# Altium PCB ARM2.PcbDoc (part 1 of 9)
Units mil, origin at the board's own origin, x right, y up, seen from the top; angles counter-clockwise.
Board outline 4700.79 x 3937.01 mil, 6 copper layers (Top Layer, GND02, ART03, ART04, PWR05, Bottom Layer); 697 components, 508 nets, 2326 pads, 1231 vias.
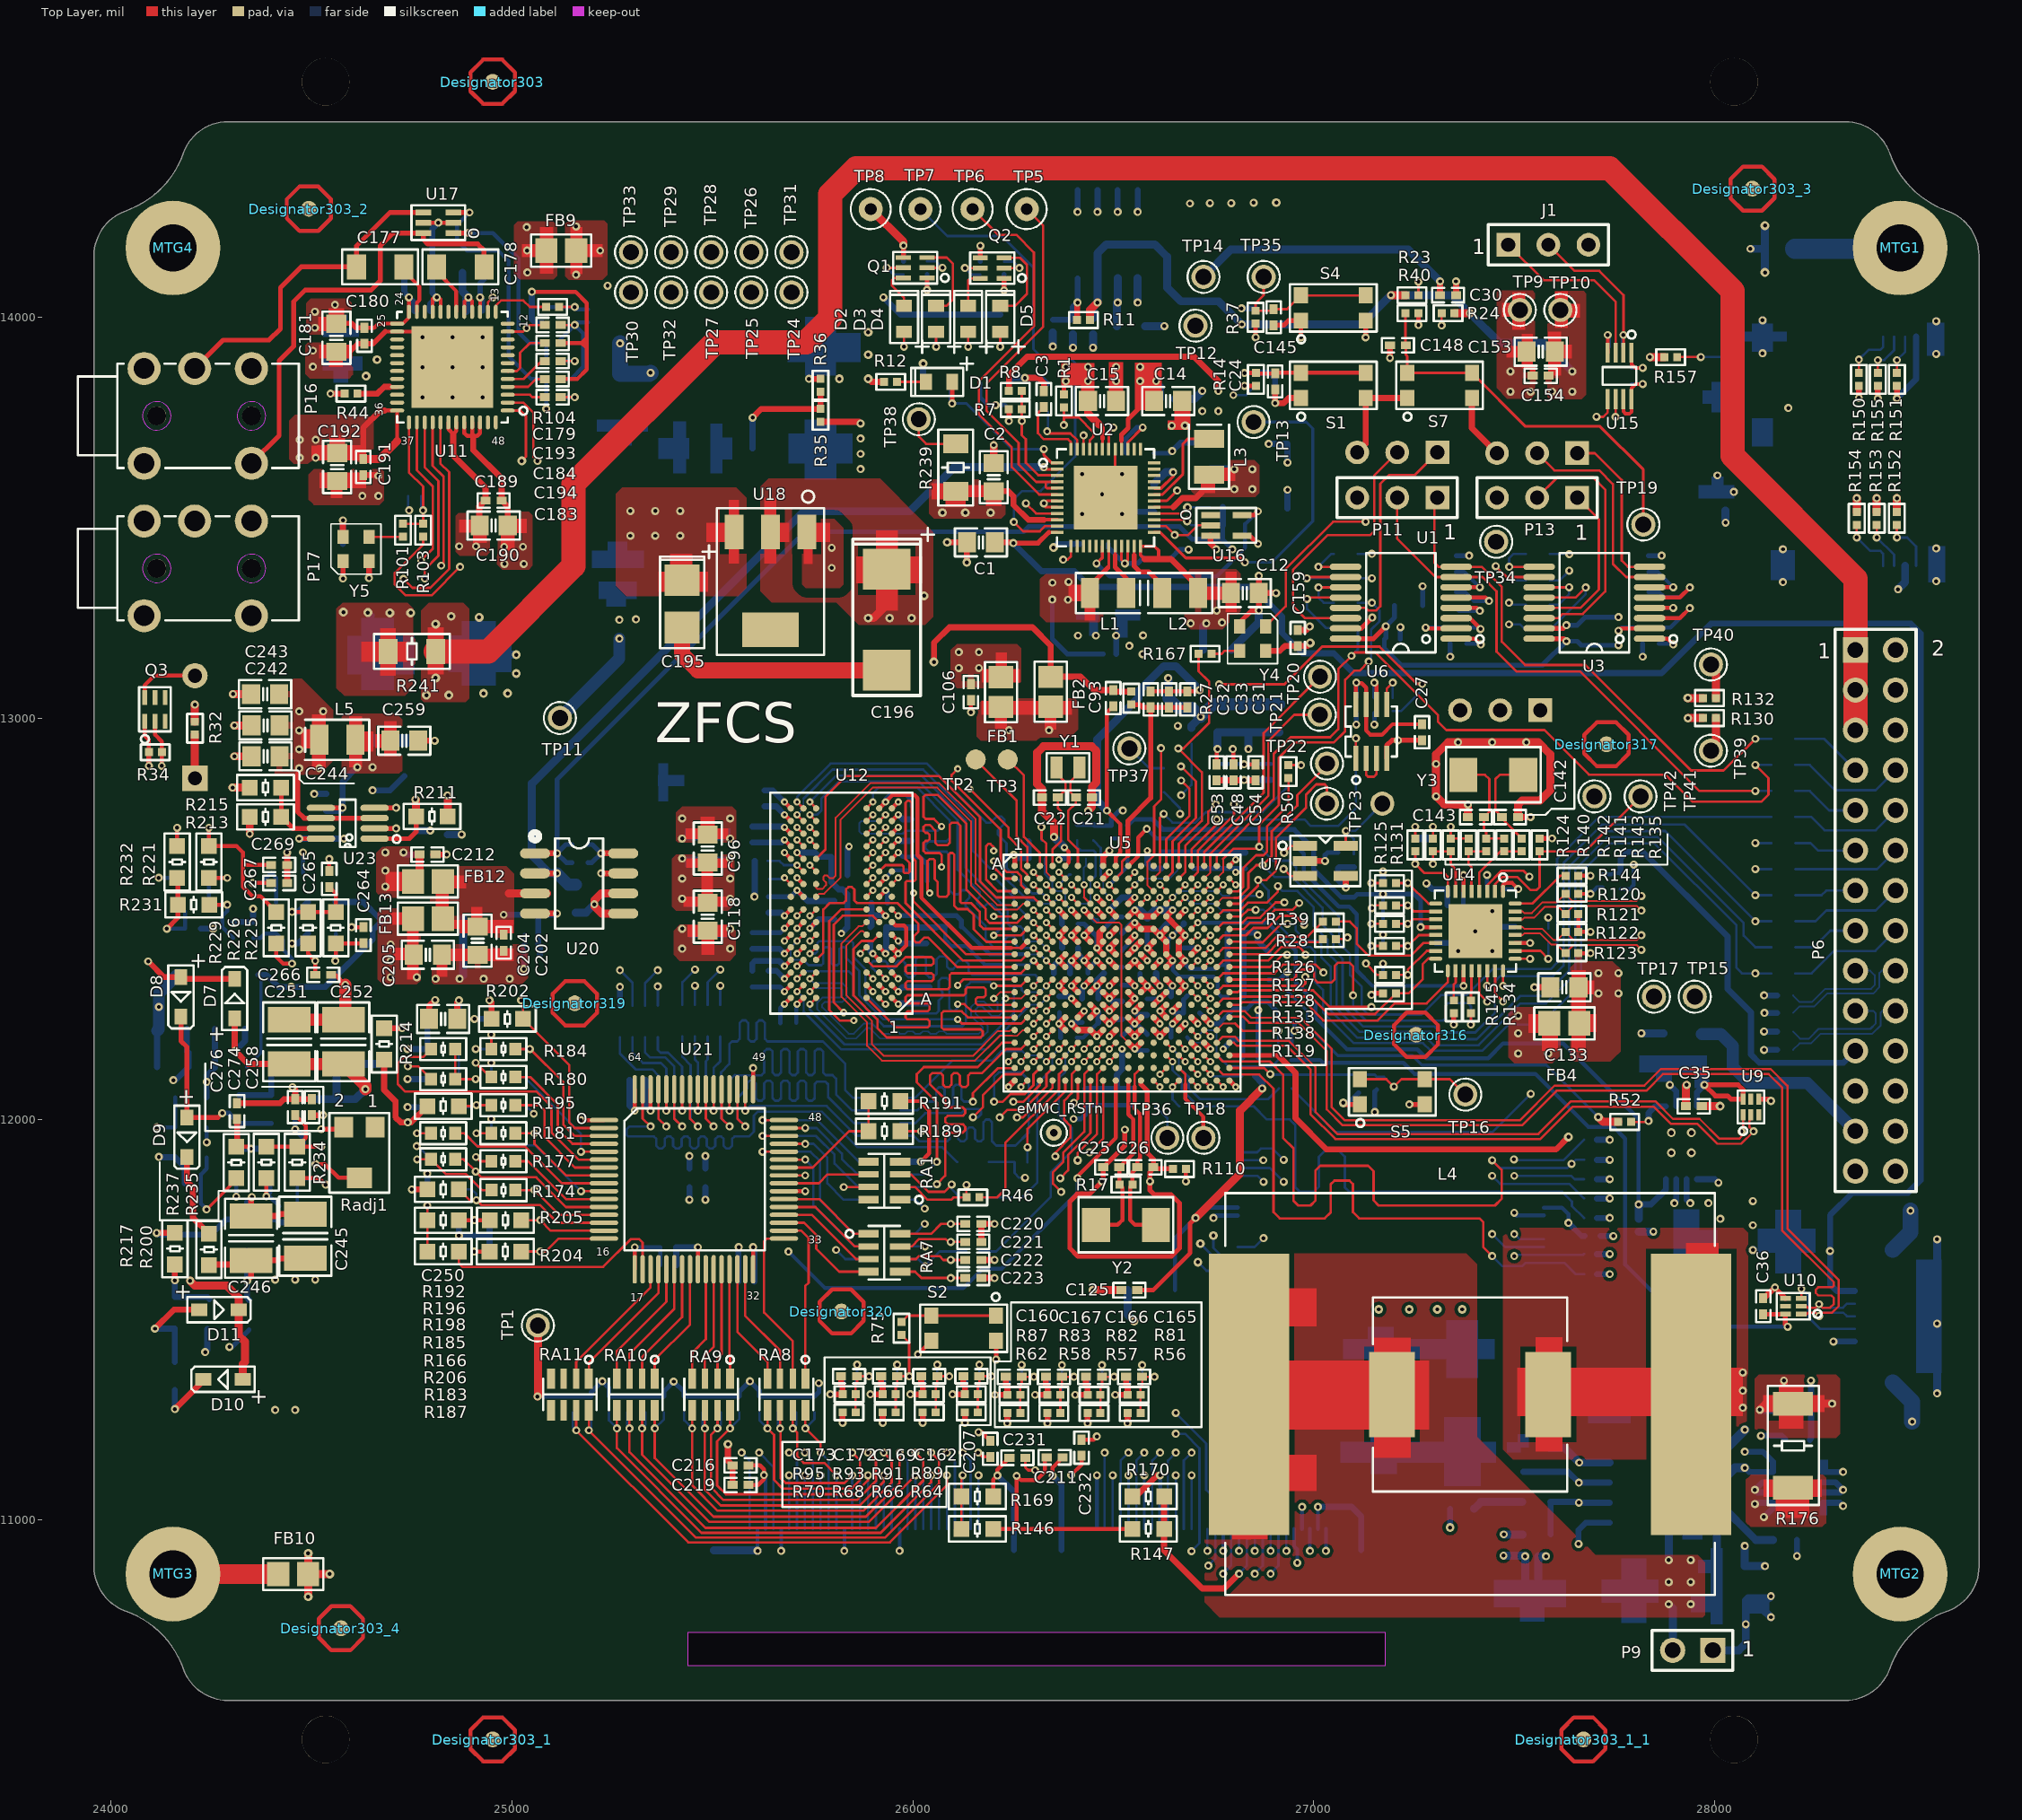
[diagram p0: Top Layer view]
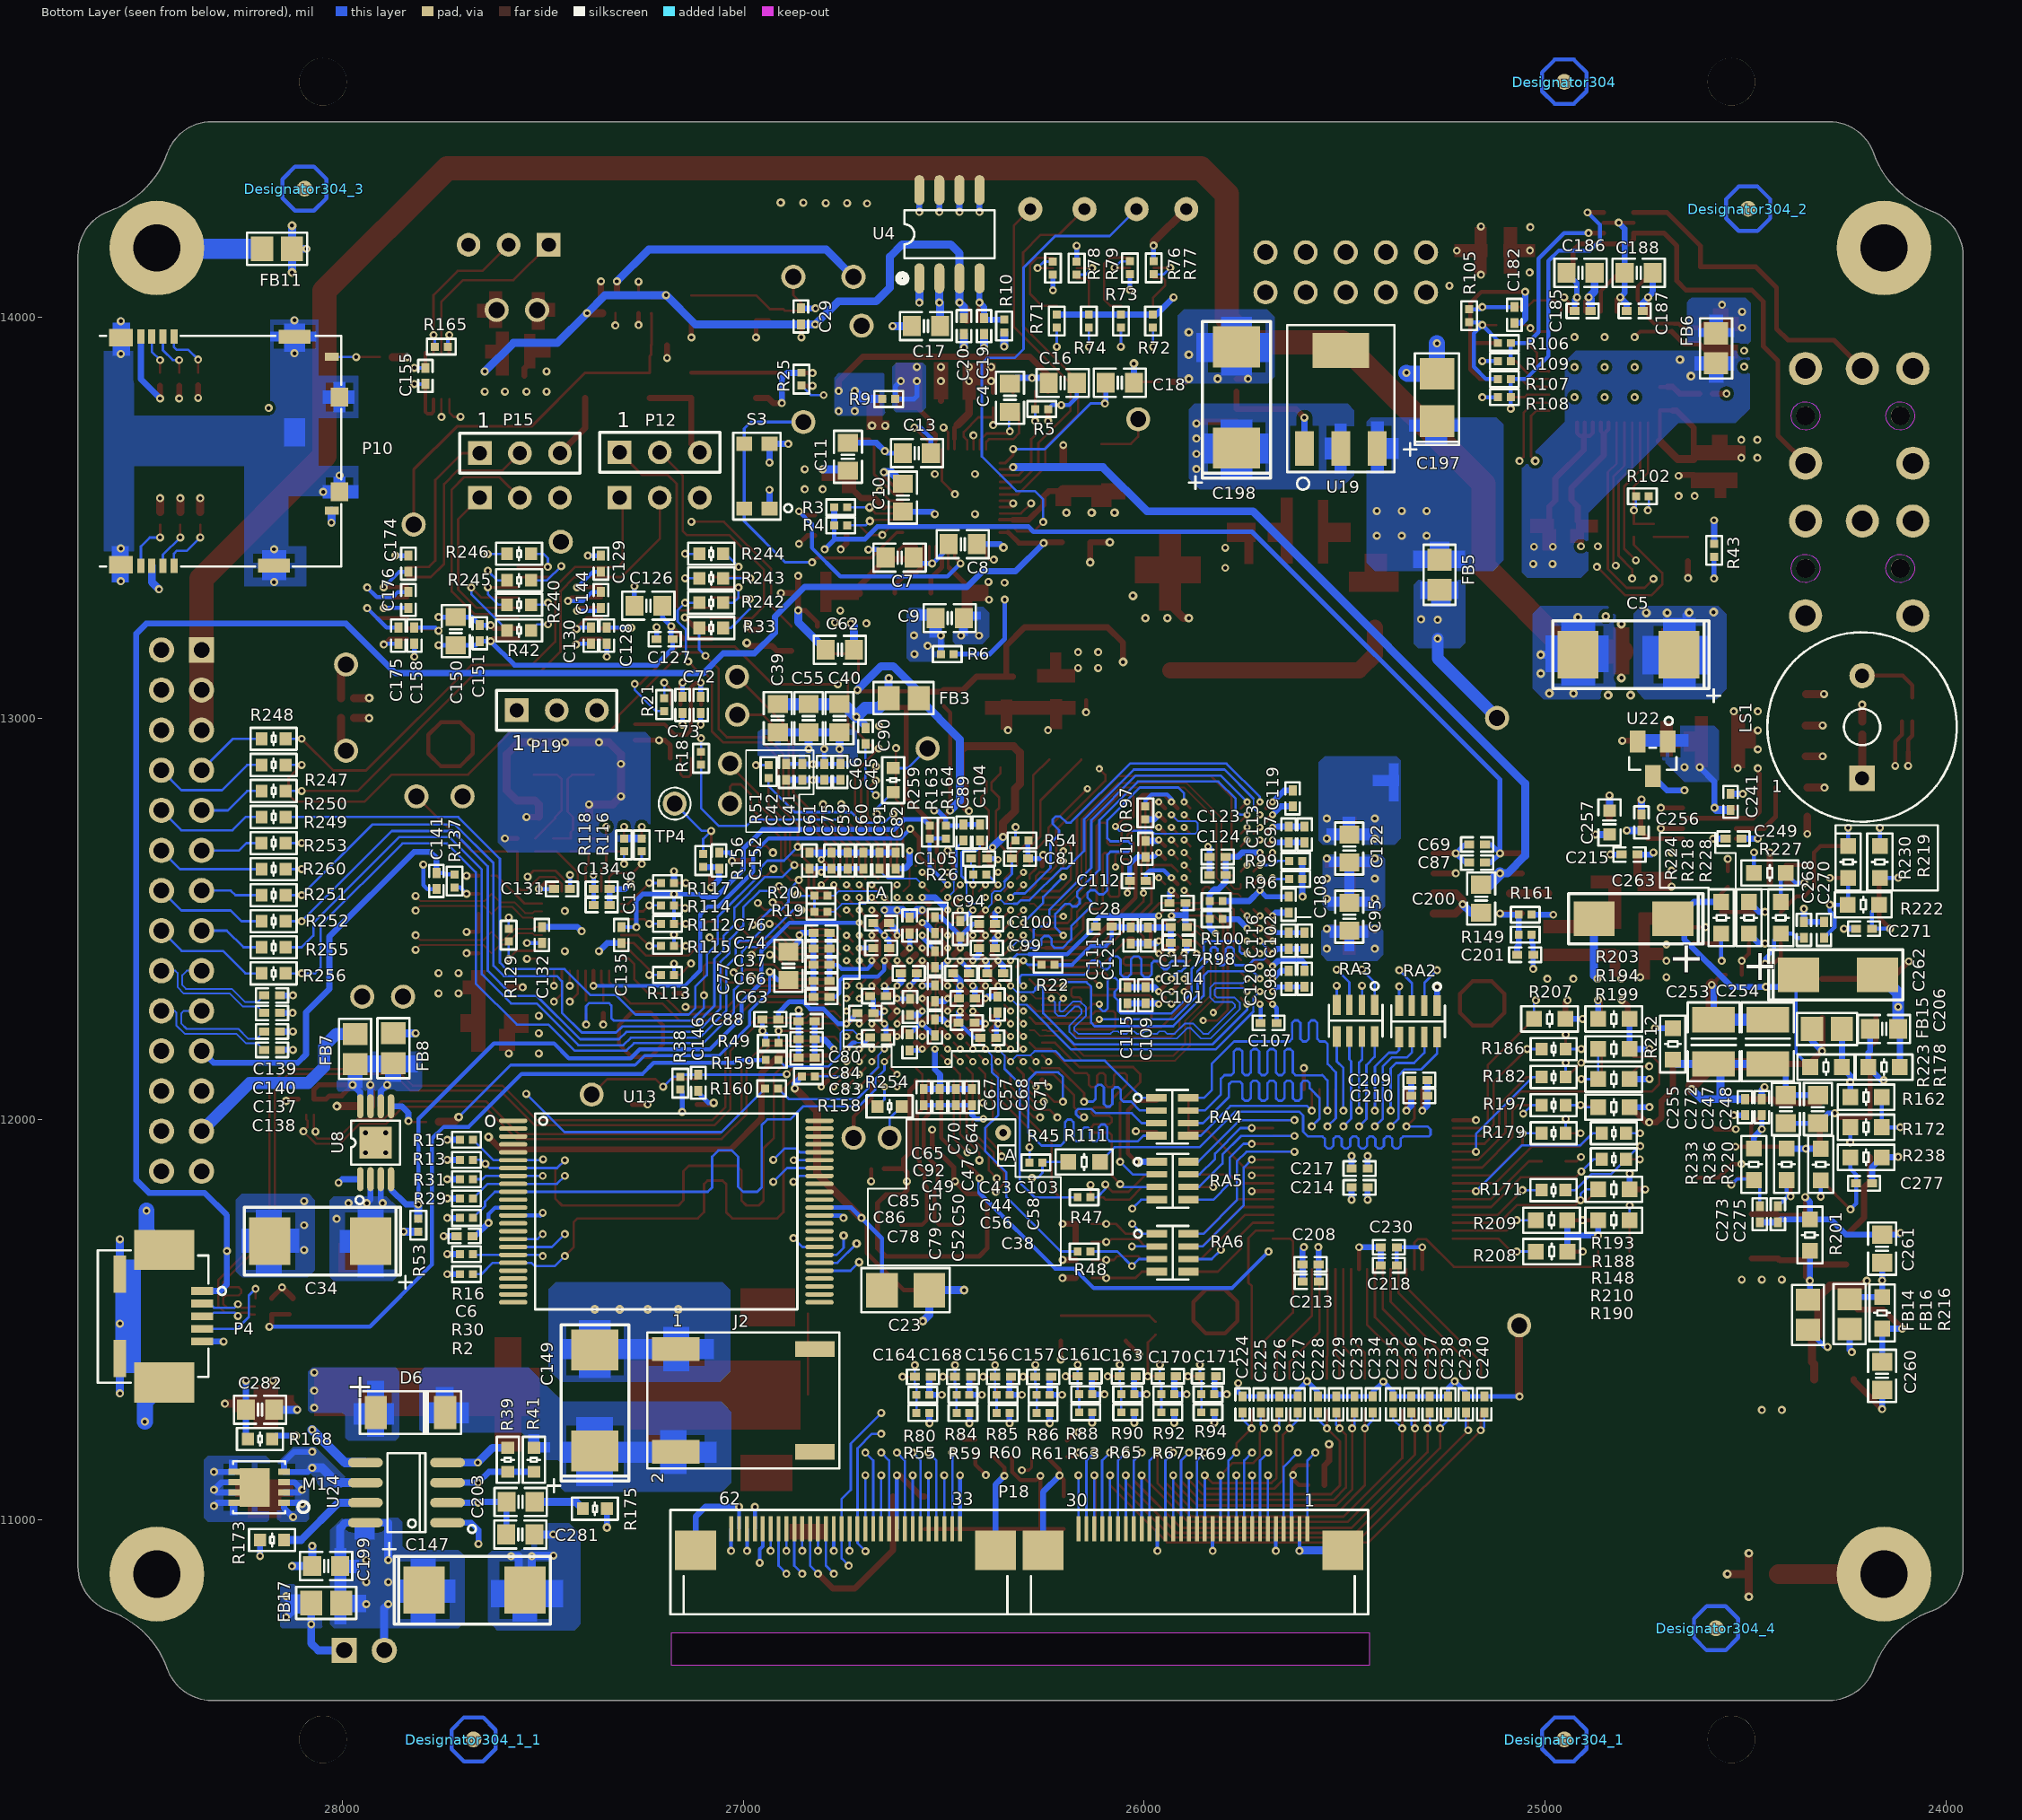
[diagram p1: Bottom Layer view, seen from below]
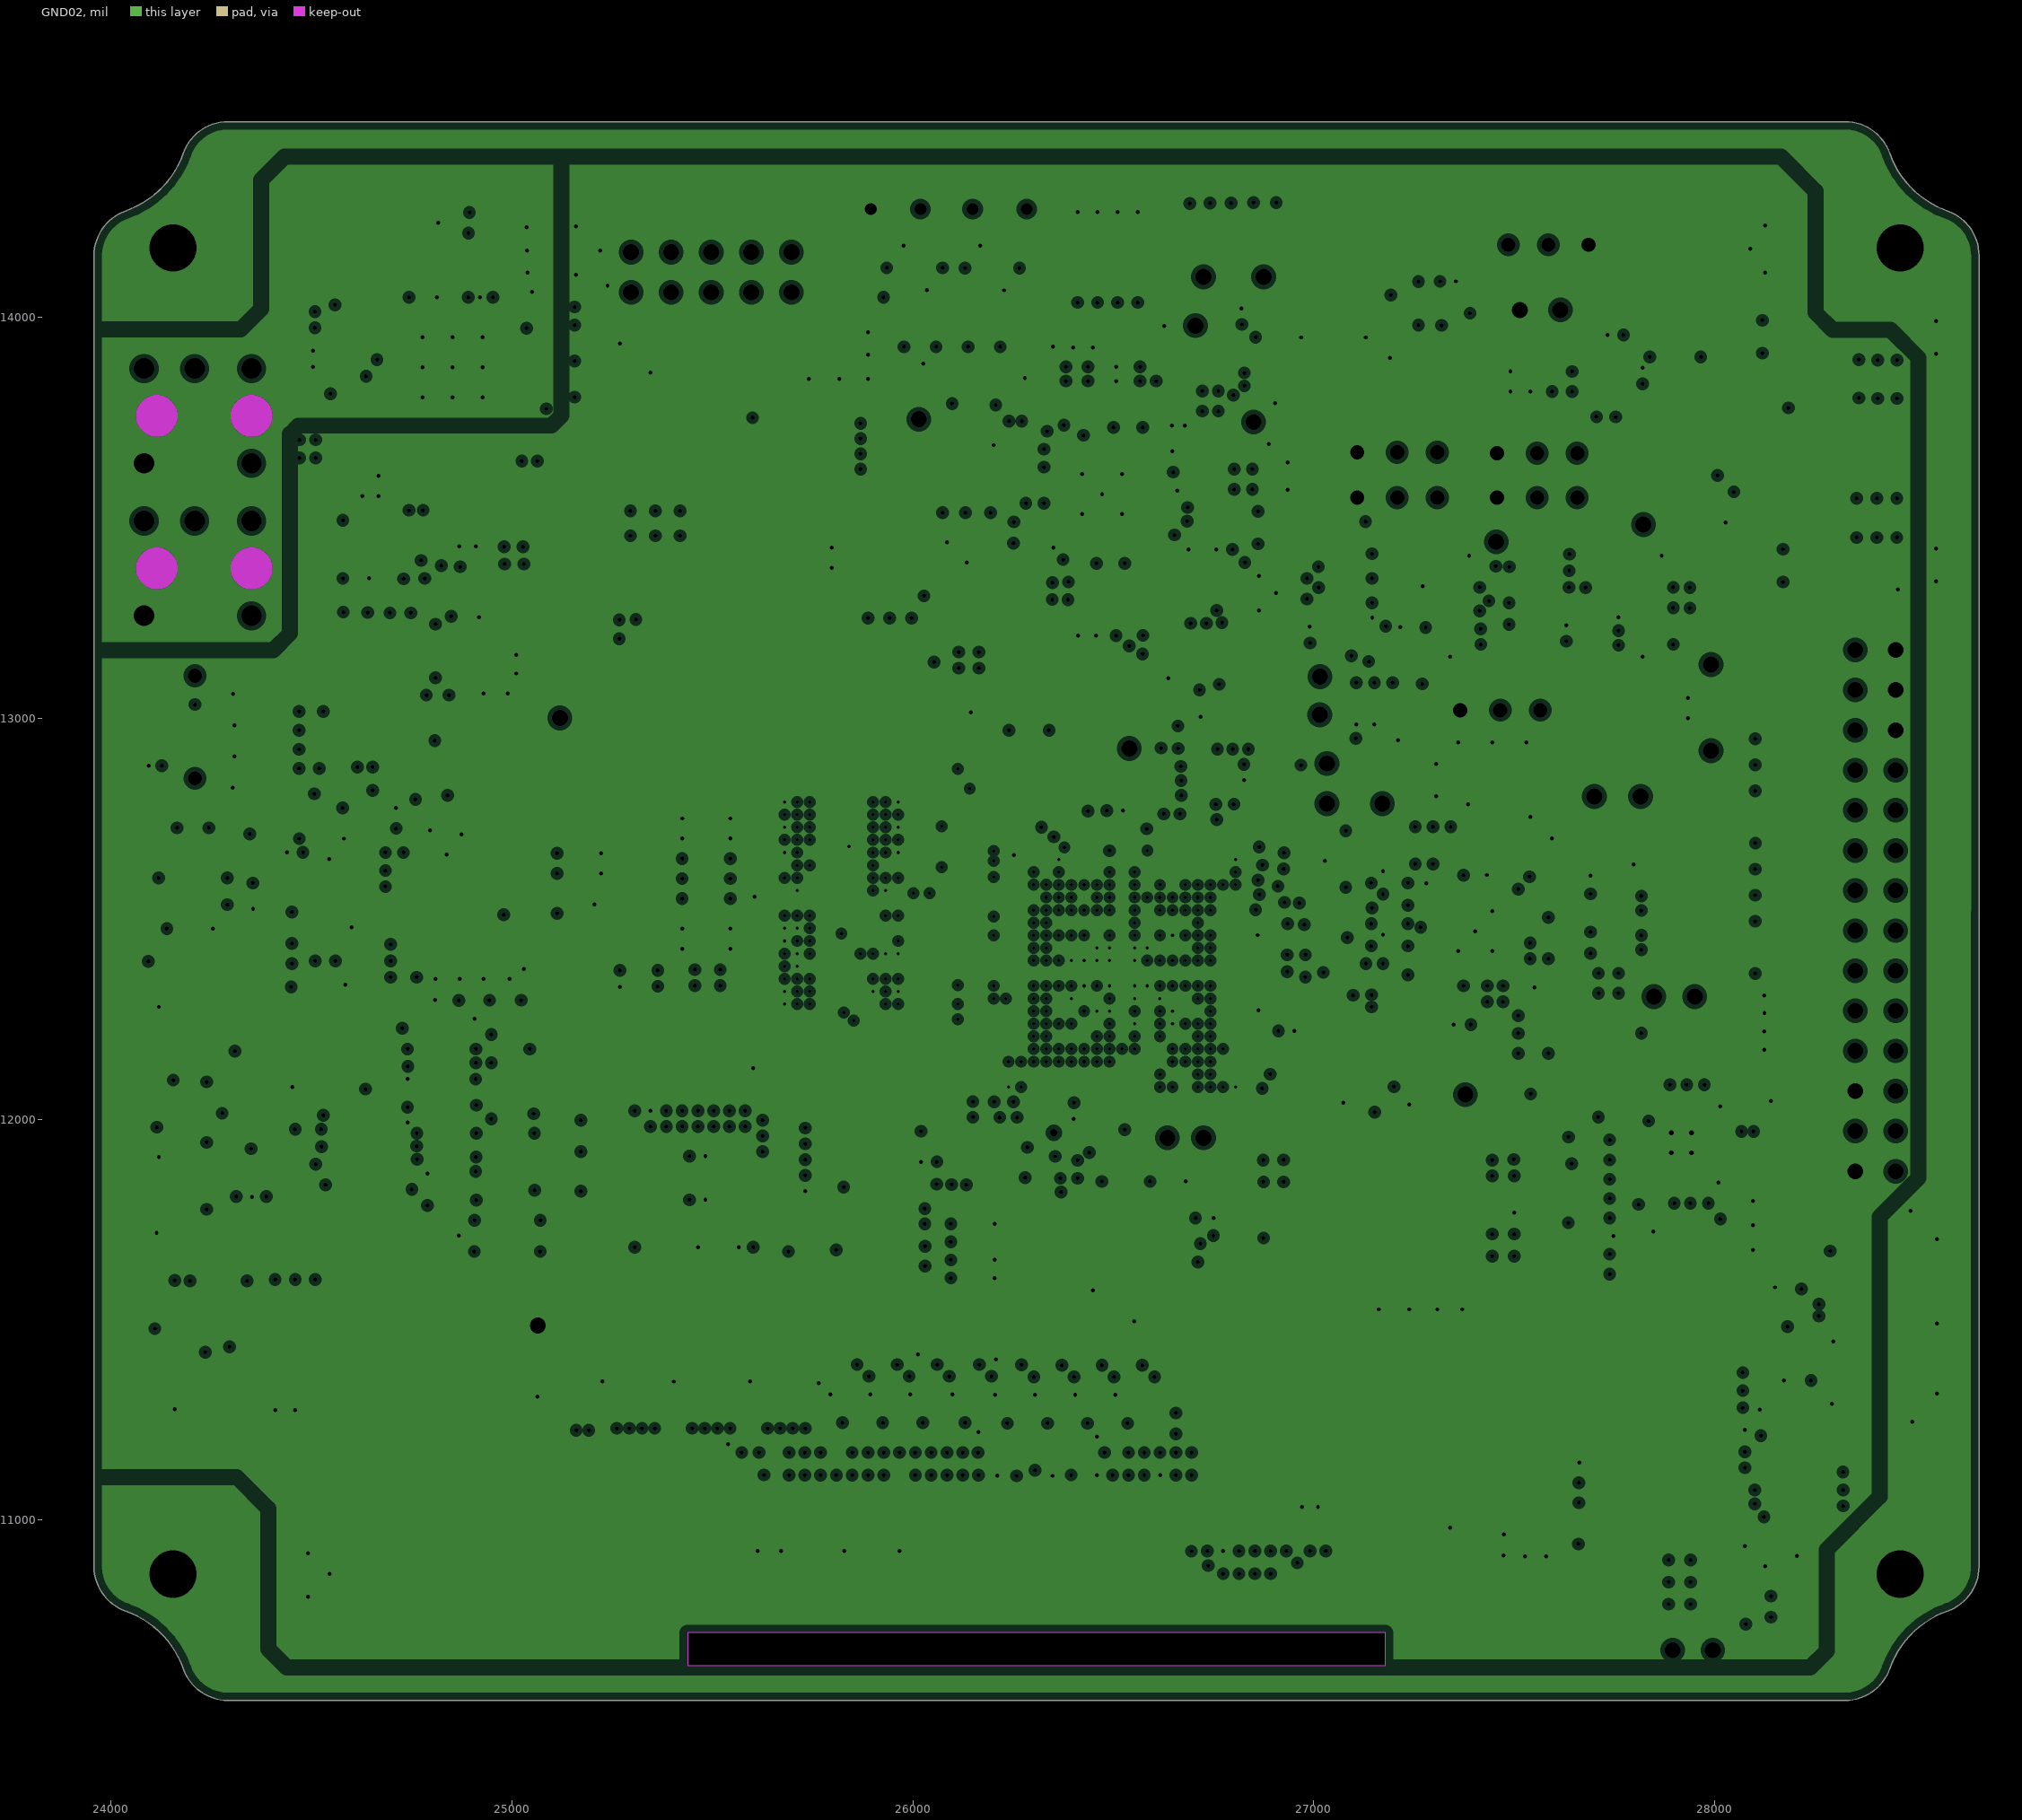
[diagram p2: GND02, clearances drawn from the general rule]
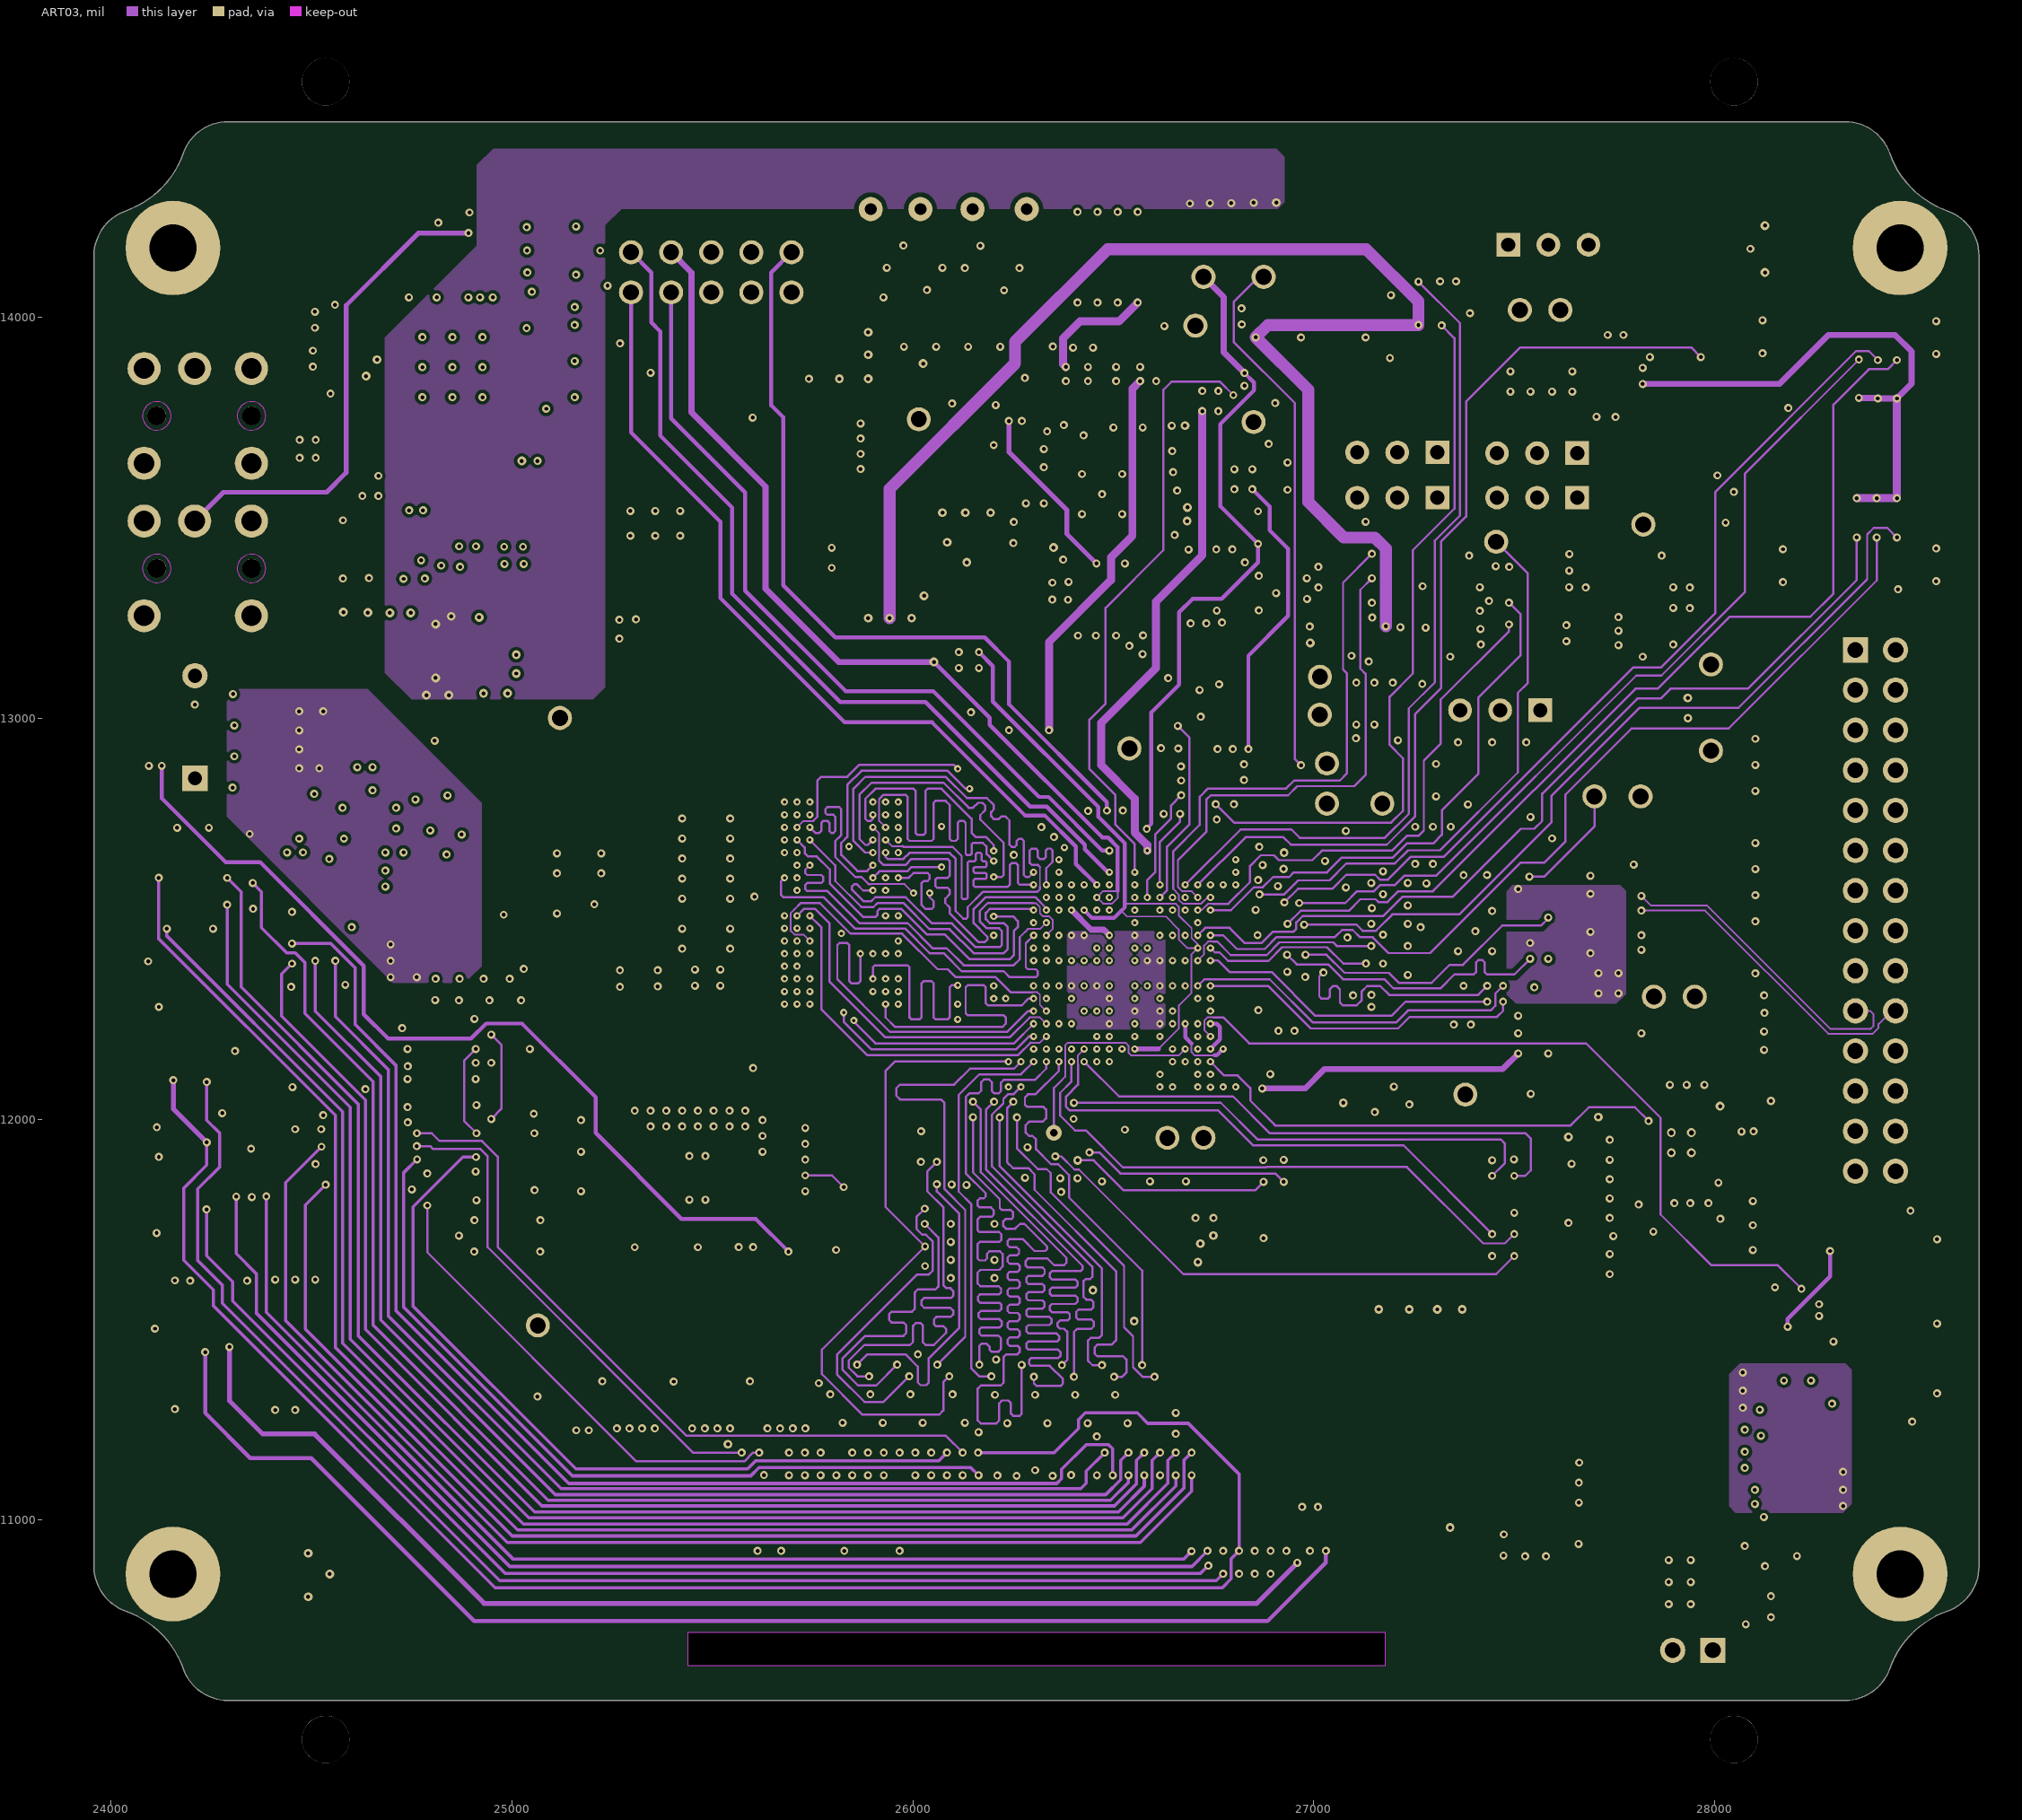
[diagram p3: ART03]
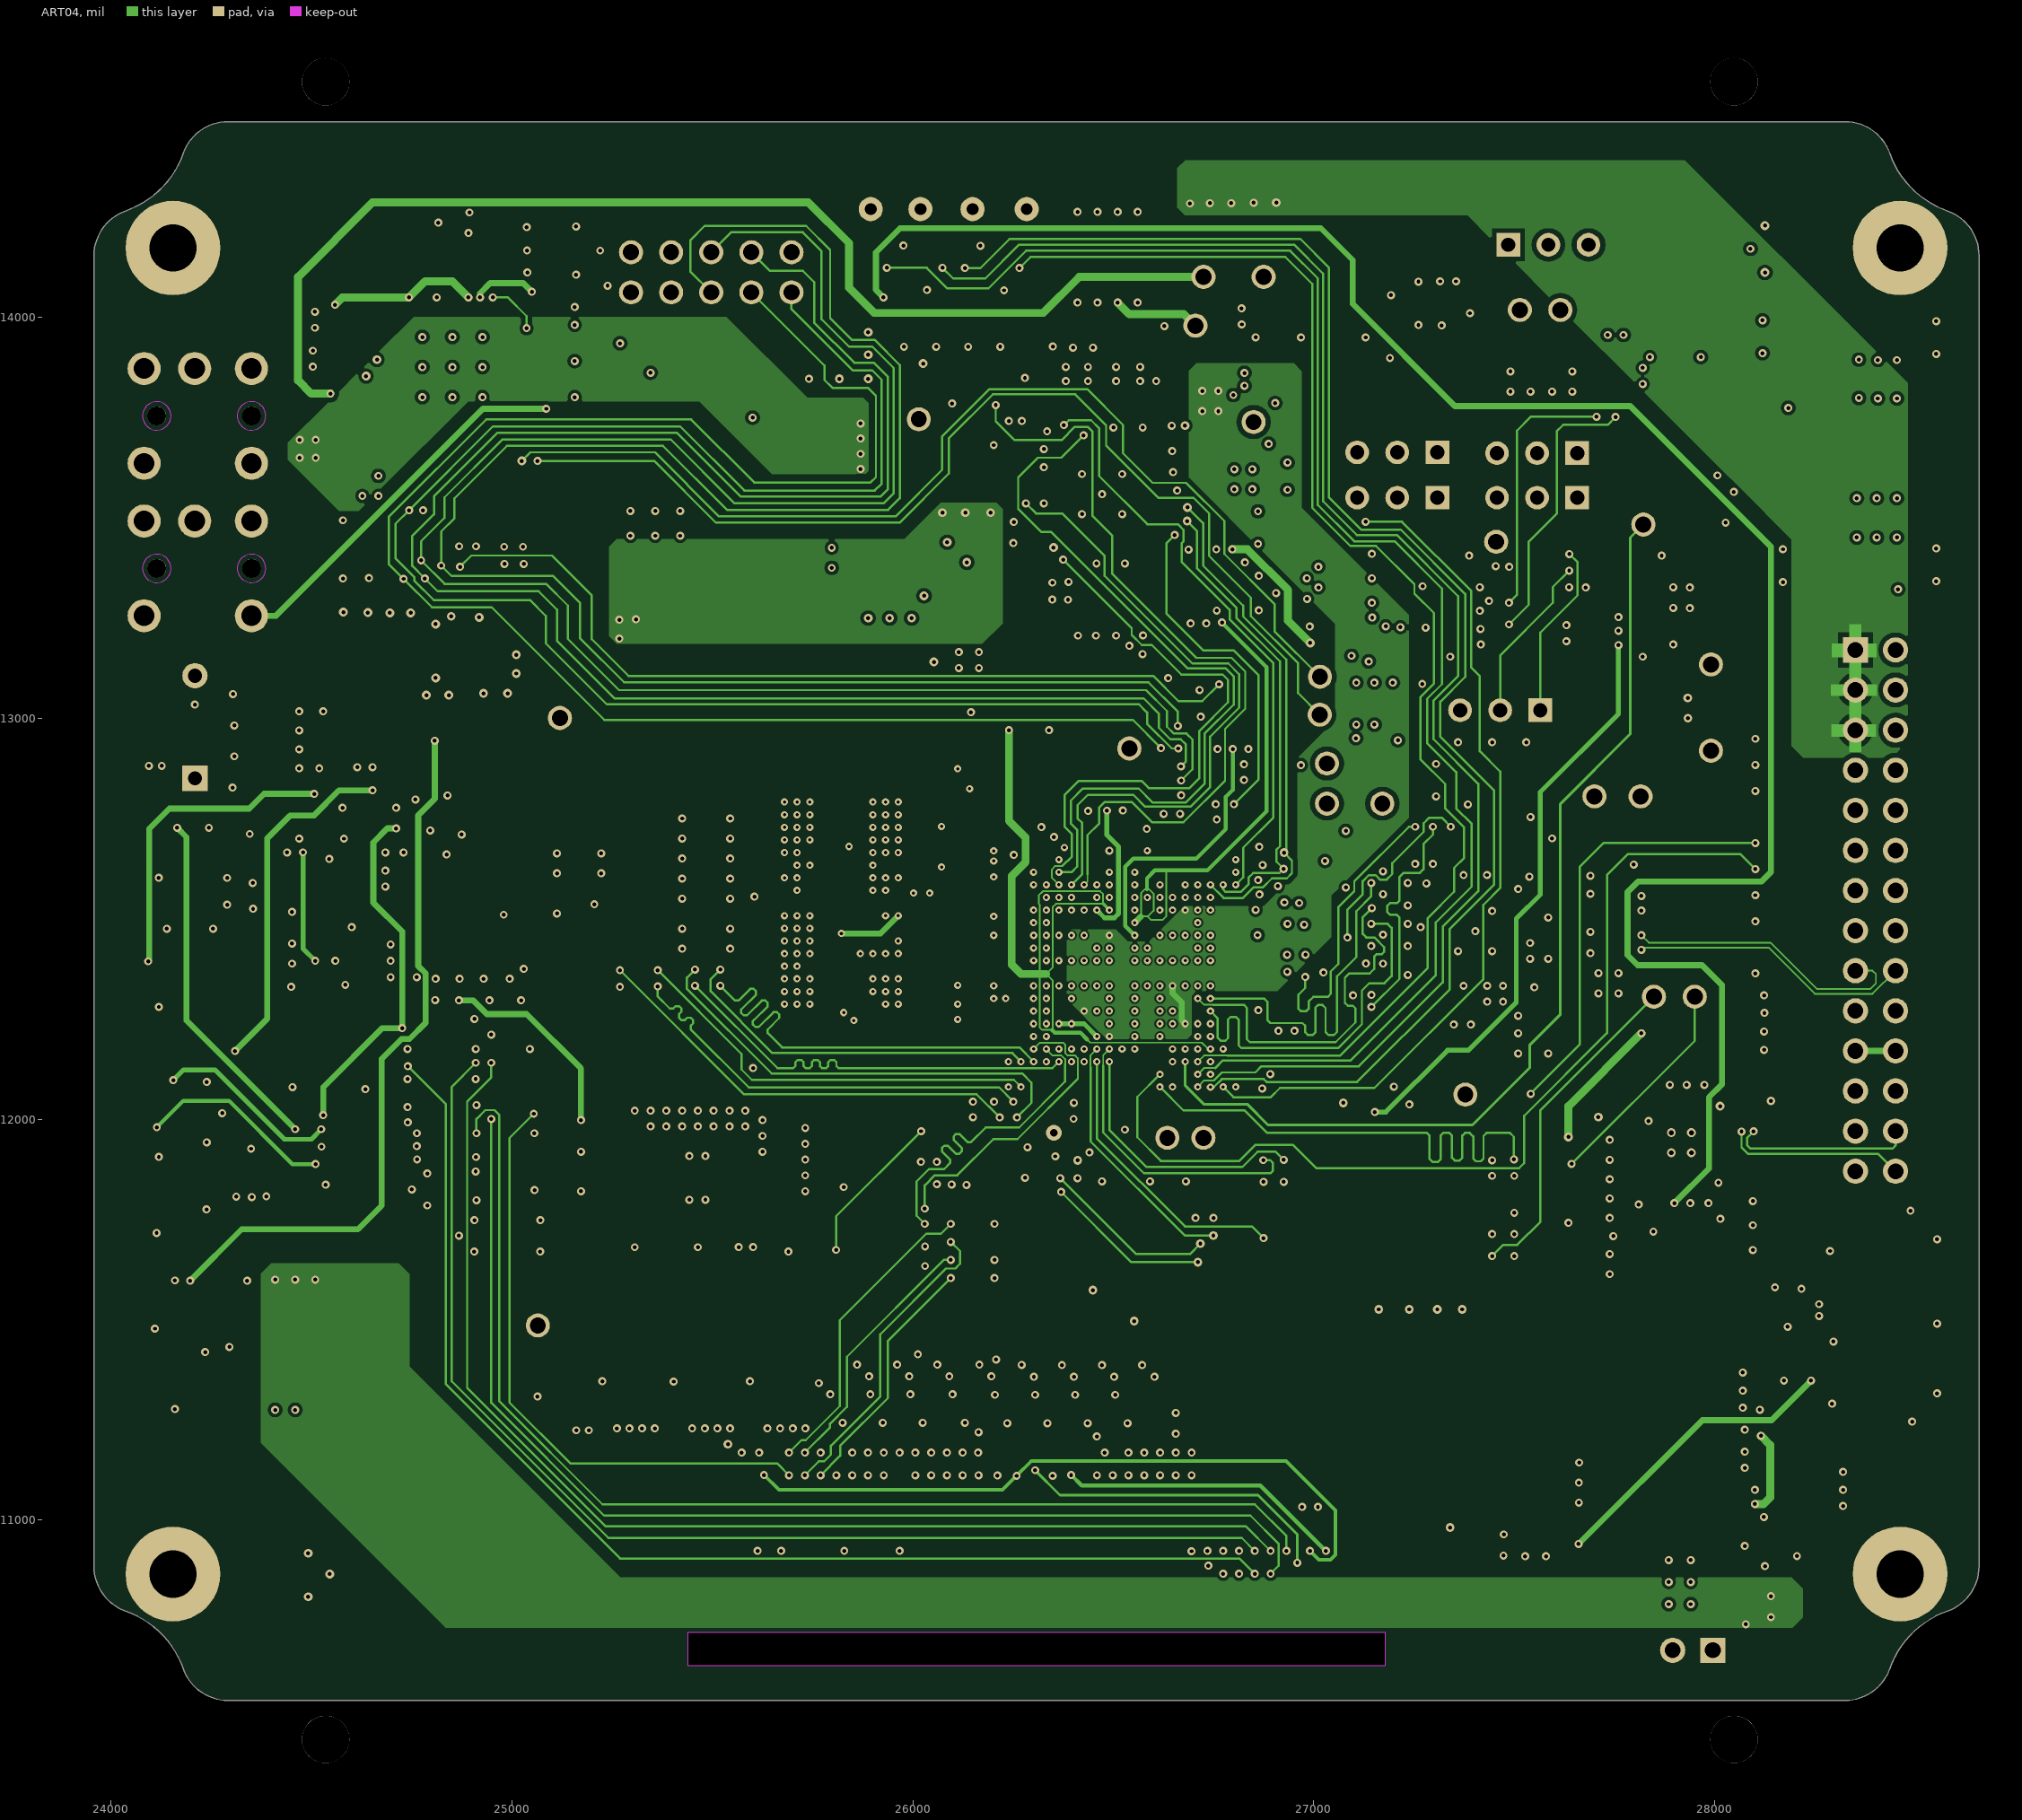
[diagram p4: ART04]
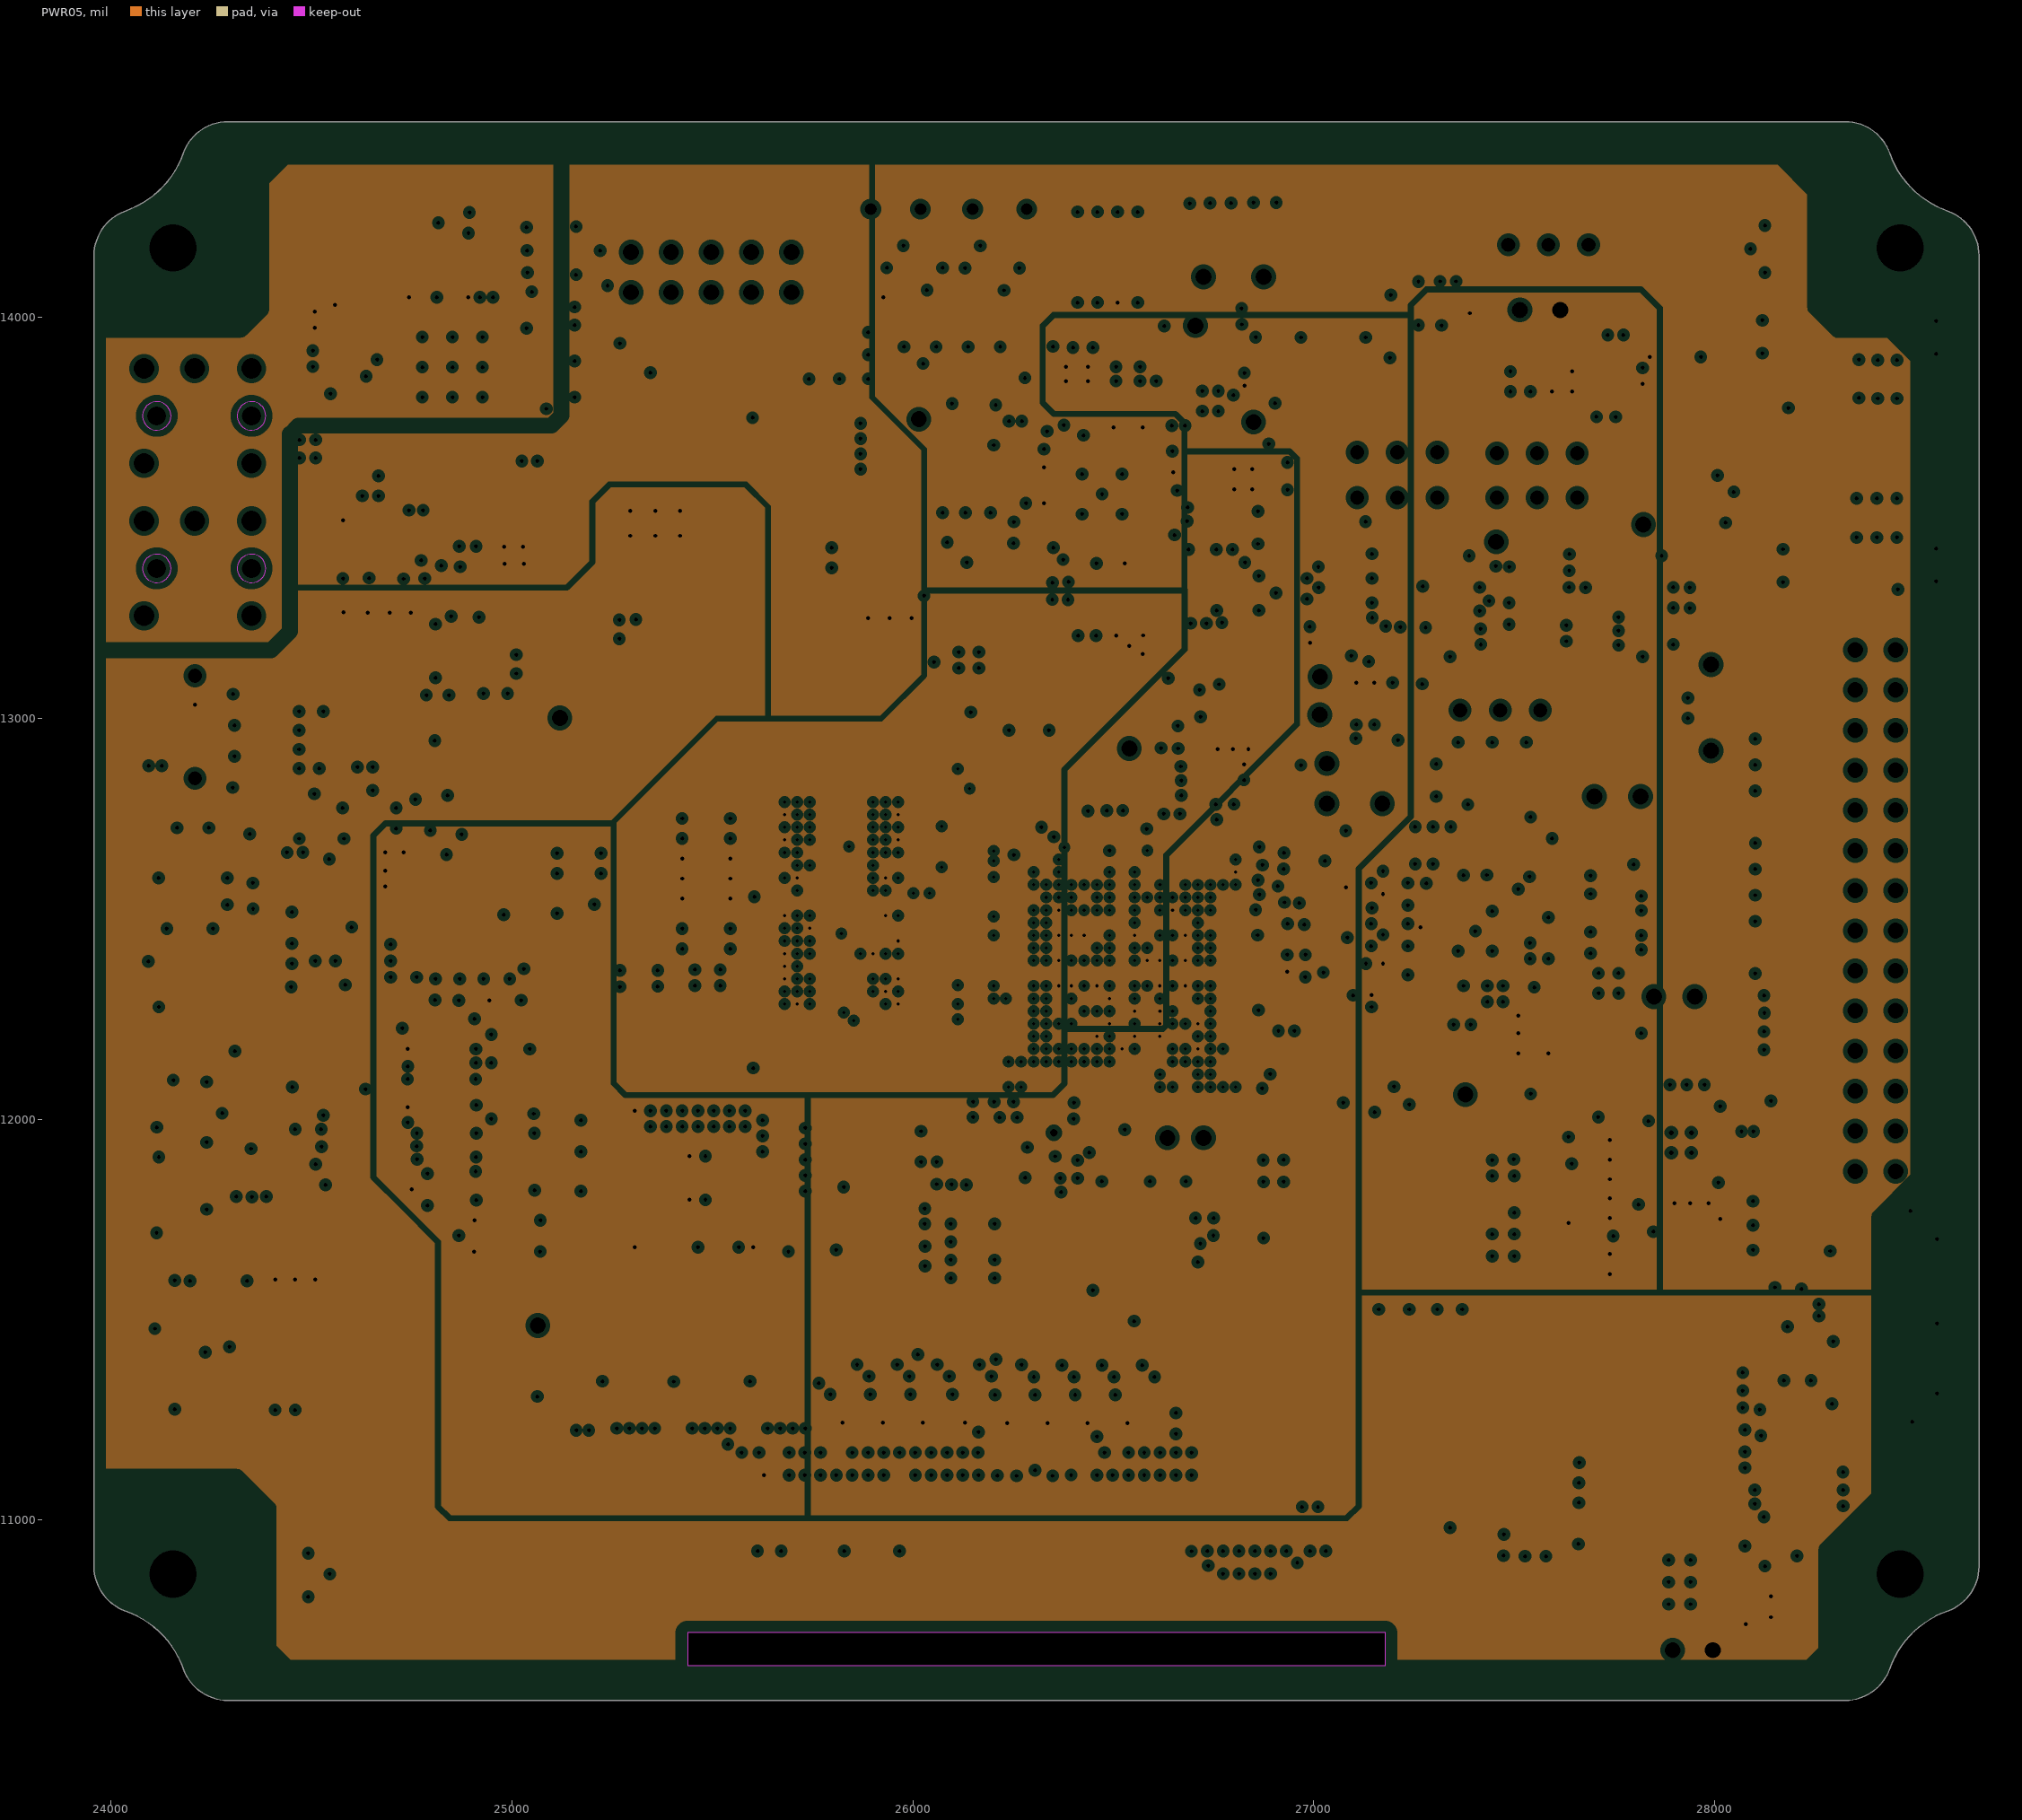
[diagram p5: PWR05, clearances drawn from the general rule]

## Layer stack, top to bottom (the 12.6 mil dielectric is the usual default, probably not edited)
Top Layer: signal copper 1.4
Dielectric: core 12.6, FR-4, Dk 4.8
GND02: plane copper 1.4, net (Multiple Nets)
Dielectric: prepreg 12.6, FR-4, Dk 4.8
ART03: signal copper 1.4
Dielectric: core 12.6, FR-4, Dk 4.8
ART04: signal copper 1.4
Dielectric: prepreg 12.6, FR-4, Dk 4.8
PWR05: plane copper 1.4, net (Multiple Nets)
Dielectric: core 12.6, FR-4, Dk 4.8
Bottom Layer: signal copper 1.4

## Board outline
23958.27,10884.68 ccw(c24076.39,10884.68) 24037.01,10773.32 cw(c23958.27,10550.61) 24180.99,10629.35 ccw(c24292.34,10668.72) 24292.34,10550.61 28325,10550.61 ccw(c28325,10668.72) 28436.35,10629.35 cw(c28659.06,10550.62) 28580.32,10773.32 ccw(c28540.95,10884.68) 28659.06,10884.68 28659.06,14153.56 ccw(c28540.95,14153.56) 28580.32,14264.91 cw(c28659.06,14487.62) 28436.35,14408.88 ccw(c28325,14369.52) 28325,14487.62 24292.34,14487.62 ccw(c24292.34,14369.51) 24180.99,14408.88 cw(c23958.27,14487.62) 24037.01,14264.91 ccw(c24076.38,14153.56) 23958.27,14153.56
cut-out: 25438.35,10638.25 27178.5,10638.25 27178.5,10719.25 25438.35,10719.25

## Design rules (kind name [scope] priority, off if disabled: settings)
Clearance room [withinroom('room1') or  withinroom('room2')] p1: gap=4.3
Clearance via-poly [inpoly vs isvia] p2: gap=8
Clearance poly-poly [inpoly vs inpoly] p3: gap=20
Clearance all-poly [inpoly] p4: gap=12
Clearance via-pad [isvia vs ispad] p5: gap=7
Clearance [All] p6: gap=5
DiffPairsRouting 111 [(InDifferentialPairClass('All Differential Pairs'))  or withinroom('room1')] p1 off: maxlimit=4.5 minlimit=4.5 mostfreqgap=4.5 maxuncoupledlength=500
DiffPairsRouting Diff100ohm [(InDifferentialPairClass('diff100'))] p2: maxlimit=8 minlimit=7.5 mostfreqgap=8 toplayer_maxgap=7.5 toplayer_prefgap=7.5 midlayer1_mingap=8 midlayer2_mingap=8 bottomlayer_maxgap=7.5 bottomlayer_prefgap=7.5 maxuncoupledlength=500
DiffPairsRouting diff90ohm [(InDifferentialPairClass('diff90'))] p3: maxlimit=8 minlimit=7 mostfreqgap=8 toplayer_maxgap=7 toplayer_prefgap=7 midlayer1_mingap=8 midlayer2_mingap=8 bottomlayer_maxgap=7 bottomlayer_prefgap=7 maxuncoupledlength=500
FabricationTestpoint [(IsPad And (OnTopLayer Or OnBottomLayer))] p1: side=3 testpointundercomponent=TRUE minsize=40 maxsize=100 preferedsize=60 minholesize=0 maxholesize=40 preferedholesize=32 testpointgrid=1 allowsidetop=TRUE allowsidebottom=TRUE usegrid=TRUE gridtolerance=0.01
MinimumSolderMaskSliver [All] p1: minsoldermaskwidth=2.5
NetAntennae [All] p1: netantennaetolerance=1
PlaneClearance PlaneClearance_1 [withinroom('room1') or  withinroom('room2')] p1: clearance=7
PlaneClearance [All] p2: clearance=11
PlaneConnect PlaneConnect_2 [HasFootprint('jack_audio1')or HasFootprint('CONN3-PWR-PJ102A')or HasFootprint('MTGH200C125D_PL')or HasFootprint('USB_A_SH')or HasFootprint('RJ45-7499010211A')] p1: planeconnectstyle=Relief reliefexpansion=10 reliefentries=4 reliefconductorwidth=30 reliefairgap=10
PlaneConnect PlaneConnect_1 [withinroom('room1') or  withinroom('room2')] p2: planeconnectstyle=Direct reliefexpansion=8 reliefentries=4 reliefconductorwidth=10 reliefairgap=8
PlaneConnect [All] p3: planeconnectstyle=Relief reliefexpansion=8 reliefentries=4 reliefconductorwidth=15 reliefairgap=8
PolygonConnect PolygonConnect_via [isvia] p1: connectstyle=Direct reliefconductorwidth=10 reliefentries=4 polygonreliefangle="90 Angle"
PolygonConnect [InNetClass('PWR')] p2: connectstyle=Relief reliefconductorwidth=15 reliefentries=4 polygonreliefangle="90 Angle"
RoomDefinition Room2 [InComponentClass('Components Class 1')] p1: confinementstyle=ConfineIn formatcopy=TRUE lockcomponents=FALSE outline 25648,12822 25995,12822 25995,12263.8 25648,12263.8
RoomDefinition Room1 [All] p2: confinementstyle=ConfineOut formatcopy=TRUE lockcomponents=FALSE outline 26178.6,12650 26820.6,12650 26820.6,12065 26178.6,12065
RoutingVias [All] p1: holewidth=10 width=20 viastyle="Through Hole" minholewidth=8 minwidth=18 maxholewidth=10 maxwidth=22
SilkToSilkClearance [All] p1: silktosilkclearance=2.5
SilkscreenOverComponentPads [All] p1: minsilkscreentomaskgap=2.5
SolderMaskExpansion [All] p1: expansion=2.5
Width Width_room [withinroom('room1') or  withinroom('room2')] p1: maxlimit=100 minlimit=4.4 preferedwidth=4.4
Width roomdiff [(InDifferentialPairClass('All Differential Pairs'))  or withinroom('room1')] p2 off: maxlimit=4 minlimit=4 preferedwidth=4
Width diff90 [(InDifferentialPairClass('diff90'))] p3: maxlimit=5.5 minlimit=5.5 preferedwidth=5.5
Width diff100 [(InDifferentialPairClass('diff100'))] p4: maxlimit=4.4 minlimit=4.3 preferedwidth=4.4 toplayer_minwidth=4.4 midlayer1_maxwidth=4.3 midlayer1_prefwidth=4.3 midlayer2_maxwidth=4.3 midlayer2_prefwidth=4.3 bottomlayer_minwidth=4.4 minimp=50.000000 maximp=50.000000 favimp=50.000000
Width pwr [InNetClass('a')or InNetClass('PWR')] p5: maxlimit=200 minlimit=7 preferedwidth=20
Width 50ohm [All] p6: maxlimit=6 minlimit=5.5 preferedwidth=6 toplayer_minwidth=6 midlayer1_maxwidth=5.5 midlayer1_prefwidth=5.5 midlayer2_maxwidth=5.5 midlayer2_prefwidth=5.5 bottomlayer_minwidth=6 minimp=50.000000 maximp=50.000000 favimp=50.000000
20 further rules are at their usual default settings.

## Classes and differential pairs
net class a: AIN0 AIN1 AIN2 AIN3 AIN4 AIN5 AIN6 AIN7 AUD_HPLOUT AUD_HPLOUT_JCK AUD_HPROUT AUD_HPROUT_JCK GRN_C NetP17_2 NetP17_4 YEL_C
net class ain: AIN0 AIN1 AIN2 AIN3 AIN4 AIN5 AIN6 AIN7
net class ddr: DDR_A0 DDR_A1 DDR_A2 DDR_A3 DDR_A4 DDR_A5 DDR_A6 DDR_A7 DDR_A8 DDR_A9 DDR_A10 DDR_A11 DDR_A12 DDR_A13 DDR_A14 DDR_A15 DDR_BA0 DDR_BA1 DDR_BA2 DDR_CASN DDR_CKE DDR_CLK DDR_CLKN DDR_CSN DDR_D0 DDR_D1 DDR_D2 DDR_D3 DDR_D4 DDR_D5 DDR_D6 DDR_D7 DDR_D8 DDR_D9 DDR_D10 DDR_D11 DDR_D12 DDR_D13 DDR_D14 DDR_D15 DDR_DQM0 DDR_DQM1 DDR_DQS0 DDR_DQS1 DDR_DQSN0 DDR_DQSN1 DDR_ODT DDR_RASN DDR_RESETN DDR_VREF DDR_VTP DDR_WEN
net class flash_d: NAND_D0 NAND_D1 NAND_D2 NAND_D3 NAND_D4 NAND_D5 NAND_D6 NAND_D7
net class flash: NAND_ALE NAND_CLE NAND_CSN0 NAND_CSN3 NAND_OEN NAND_WAIT0 NAND_WAIT1 NAND_WEN NAND_WPN
net class gpio: GPIO0_7 GPIO0_7SRC GPIO0_26 GPIO0_27 GPIO1_12 GPIO1_13 GPIO1_14 GPIO1_15 GPIO1_16 GPIO1_17 GPIO1_28 GPIO3_18 GPIO3_19 GPIO3_20 GPIO3_21
net class L_B: L_BO0 L_BO1 L_BO2 L_BO3 L_BO4 L_BO5
net class L_G: L_GO0 L_GO1 L_GO2 L_GO3 L_GO4 L_GO5
net class L_R: L_REV L_RLB L_RO0 L_RO1 L_RO2 L_RO3 L_RO4 L_RO5
net class L_V: L_V1 L_V2 L_V3 L_V4 L_V5 L_V6 L_V7 L_V8 L_V9 L_V10 L_V11 L_V12 L_V13 L_V14 L_VCOM L_VGH L_VGL L_VLC
net class LCD_B: LCD_DATA0 LCD_DATA1 LCD_DATA2 LCD_DATA3 LCD_DATA4
net class LCD_CLK: LCD_DE LCD_HSYNC LCD_PCLK LCD_VSYNC
net class LCD_G: LCD_DATA5 LCD_DATA6 LCD_DATA7 LCD_DATA8 LCD_DATA9 LCD_DATA10
net class LCD_R: LCD_DATA11 LCD_DATA12 LCD_DATA13 LCD_DATA14 LCD_DATA15 RI_H0 RI_H1 RI_H2 RI_H3 RI_H4 RI_H5
net class lcd: CLKH LCD_DATA0 LCD_DATA1 LCD_DATA2 LCD_DATA3 LCD_DATA4 LCD_DATA5 LCD_DATA6 LCD_DATA7 LCD_DATA8 LCD_DATA9 LCD_DATA10 LCD_DATA11 LCD_DATA12 LCD_DATA13 LCD_DATA14 LCD_DATA15 LCD_DE LCD_HSYNC LCD_PCLK LCD_VSYNC LCDDE LCDPCLK LCDVHYNC LCDVSYNC RI_H1 RI_H2 RI_H3 RI_H4 RI_H5
net class MII1_RX: MII1_RXCLK MII1_RXD0 MII1_RXD1 MII1_RXD2 MII1_RXD3 MII1_RXDV
net class MII1_TX: MII1_TXCLK MII1_TXD0 MII1_TXD1 MII1_TXD2 MII1_TXD3
net class mll1: MII1_COL MII1_CRS_DV MII1_REFCLK MII1_RXCLK MII1_RXD0 MII1_RXD1 MII1_RXD2 MII1_RXD3 MII1_RXDV MII1_RXERR MII1_TXCLK MII1_TXD0 MII1_TXD1 MII1_TXD2 MII1_TXD3 MII1_TXEN
net class "New Class": LCD_DATA0 LCD_DATA1 LCD_DATA2 LCD_DATA3 LCD_DATA4 LCD_DATA5 LCD_DATA6 LCD_DATA7 LCD_DATA8 LCD_DATA9 LCD_DATA10 LCD_DATA11 LCD_DATA12 LCD_DATA13 LCD_DATA14 LCD_DATA15 LCD_DE LCD_HSYNC LCD_PCLK LCD_VSYNC LCDDE LCDPCLK LCDVHYNC LCDVSYNC
net class PWR: 3V3_AUD AGND_AUD AUD_HPLOUT_JCK AUD_HPROUT_JCK AUD_RESETN DDR_RESETN DDR_VREF DGND EHRPWM1A EHRPWM1B GND_EARTH GND_OSC0 GND_OSC1 GNDA_ADC L_V3 L_VCOM L_VGH L_VGL NetC195_2 NetC201_1 NetC247_1 NetC247_2 NetC255_1 NetC259_2 NetC262_1 NetC272_1 NetD6_1 NetP17_2 NetP17_4 NetR35_2 NetR162_2 P_L1 P_L2 P_L3 PHY_VDDCR PWR_BUT RESET RXP SYS_5V SYS_RESETN TCT_RCT TXP USB1_DP USB1_DRVVBUS USB1_PWR USB1_VBUS USB_DC VBUS VCCD VCCD_3V3A VDCDC1 VDD_1V8 VDD_1V8B VDD_3V3A VDD_3V3AUX VDD_3V3B VDD_3V3C VDD_3V3D VDD_5V VDD_5V0 VDD_ADC VDD_CORE VDD_MPU VDD_PHYA VDD_PLL VDDS VDDS_DDR VIO VREFP_ADC
net class spi1: SPI1_CS0 SPI1_D0 SPI1_D1 SPI1_SCLK
component class P11_SDcard: C152 C153 C154 P10 R150 R151 R152 R153 R154 R155 R156 R157 TP4 TP9 TP10 TP11 TP12 TP13 TP14 TP15 TP16 TP17 TP18 TP19 TP20 TP21 TP22 TP23 TP24 TP25 TP26 TP27 TP28 TP29 TP30 TP31 TP32 TP33 TP34 TP35 U7
component class P12_Exp_Audio: C5 C126 C127 C128 C129 C130 C144 C145 C146 C148 C150 C151 C158 C174 C175 C176 C177 C178 C179 C180 C181 C182 C183 C184 C185 C186 C187 C188 C189 C190 C191 C192 C193 C194 C195 C196 C197 C198 FB5 FB6 FB9 LS1 P6 P11 P12 P13 P15 P16 P17 P19 Q3 R32 R33 R34 R35 R36 R37 R38 R40 R42 R43 R44 R101 R102 R103 R104 R105 R106 R107 R108 R109 R240 R241 R242 R243 R244 R245 R246 R247 R248 R249 R250 R251 R252 R253 R254 R255 R256 R259 R260 S4 S5 S7 U1 U3 U11 U17 U18 U19 Y5
component class P10_LCD: C156 C157 C160 C161 C162 C163 C164 C165 C166 C167 C168 C169 C170 C171 C172 C173 C199 C200 C201 C202 C203 C204 C205 C206 C207 C208 C209 C210 C211 C212 C213 C214 C215 C216 C217 C218 C219 C220 C221 C222 C223 C224 C225 C226 C227 C228 C229 C230 C231 C232 C233 C234 C235 C236 C237 C238 C239 C240 C241 C242 C243 C244 C245 C246 C247 C248 C249 C250 C251 C252 C253 C254 C255 C256 C257 C258 C259 C260 C261 C262 C263 C264 C265 C266 C267 C268 C269 C270 C271 C272 C273 C274 C275 C276 C277 D6 D7 D8 D9 D10 D11 FB12 FB13 FB14 FB15 FB16 J2 L4 L5 P18 R111 R146 R147 R148 R149 R158 R161 R162 R166 R168 R169 R170 R171 R172 R173 R174 R175 R176 R177 R178 R179 R180 R181 R182 R183 R184 R185 R186 R187 R188 R189 R190 R191 R192 R193 R194 R195 R196 R197 R198 R199 R200 R201 R202 R203 R204 R205 R206 R207 R208 R209 R210 R211 R212 R213 R214 R215 R216 R217 R218 R219 R220 R221 R222 R223 R224 R225 R226 R227 R228 R229 R230 R231 R232 R233 R234 R235 R236 R237 R238 RA1 RA2 RA3 RA4 RA5 RA6 RA7 RA8 RA9 RA10 RA11 Radj1 U20 U21 U22 U23 U24
component class P09_Ethernet: C131 C132 C133 C134 C135 C136 C137 C138 C139 C140 C141 C142 C143 FB4 R112 R113 R114 R115 R116 R117 R118 R119 R120 R121 R122 R123 R124 R125 R126 R127 R128 R129 R130 R131 R132 R133 R134 R135 R137 R138 R139 R140 R141 R142 R143 R144 R145 U14 Y3
component class P08_NandFlash: C6 C23 C125 R2 R13 R15 R16 R29 R30 R31 U13
component class P07_DDR3_SDRAM: C107 C108 C109 C110 C111 C112 C113 C114 C115 C116 C117 C118 C119 C120 C121 C122 C123 C124 R96 R97 R98 R99 R100 U12
component class P06_LED_BootConfig: D2 D3 D4 D5 Q1 Q2 R55 R56 R57 R58 R59 R60 R61 R62 R63 R64 R65 R66 R67 R68 R69 R70 R71 R72 R73 R74 R75 R76 R77 R78 R79 R80 R81 R82 R83 R84 R85 R86 R87 R88 R89 R90 R91 R92 R93 R94 R95 S2
component class P05_Processor3_3: C37 C38 C39 C40 C41 C42 C43 C44 C45 C46 C47 C48 C49 C50 C51 C52 C53 C54 C55 C56 C57 C58 C59 C60 C61 C62 C63 C64 C65 C66 C67 C68 C69 C70 C71 C72 C73 C74 C75 C76 C77 C78 C79 C80 C81 C82 C83 C84 C85 C86 C87 C88 C89 C90 C91 C92 C93 C94 C95 C96 C97 C98 C99 C100 C101 C102 C103 C104 C105 C106 FB1 FB2 FB3 R54 TP2 TP3
component class P04_Processor2_3: C31 C32 C33 C34 C35 C36 C155 FB7 FB8 J1 P4 R26 R27 R28 R45 R46 R47 R48 R49 R50 R51 R52 R53 R159 R163 R164 R165 U8 U9 U10 U15
component class P03_Processor1_3: C21 C22 C24 C25 C26 C27 C28 C29 C30 C159 R14 R17 R18 R19 R20 R21 R22 R23 R24 R25 R110 R160 R167 S1 U5 U6 U16 Y1 Y2 Y4
component class P02_PowerManagement: C1 C2 C3 C4 C7 C8 C9 C10 C11 C12 C13 C14 C15 C16 C17 C18 C19 C20 D1 FB10 FB11 L1 L2 L3 MTG1 MTG2 MTG3 MTG4 R1 R3 R4 R5 R6 R7 R8 R9 R10 R11 R12 R239 S3 TP1 TP5 TP6 TP7 TP8 U2 U4
net class DDR_BA[2..0]: DDR_BA0 DDR_BA1 DDR_BA2
net class DDR_D[15..0]: DDR_D0 DDR_D1 DDR_D2 DDR_D3 DDR_D4 DDR_D5 DDR_D6 DDR_D7 DDR_D8 DDR_D9 DDR_D10 DDR_D11 DDR_D12 DDR_D13 DDR_D14 DDR_D15
net class DDR_A[15..0]: DDR_A0 DDR_A1 DDR_A2 DDR_A3 DDR_A4 DDR_A5 DDR_A6 DDR_A7 DDR_A8 DDR_A9 DDR_A10 DDR_A11 DDR_A12 DDR_A13 DDR_A14 DDR_A15
differential pair class diff90: D_USB0_D D_USB1_D
differential pair class diff100: D_RX D_TX ddr_clk ddr_dqs1 ddr_dqsn0 i2c0 i2c1 i2c2 NewDifferentialPair1 NewDifferentialPair2
differential pair NewDifferentialPair2: +RXN -RXP
differential pair NewDifferentialPair1: +TXN -TXP
differential pair ddr_dqs1: +DDR_DQS1 -DDR_DQSN1
differential pair ddr_dqsn0: +DDR_DQSN0 -DDR_DQS0
differential pair ddr_clk: +DDR_CLKN -DDR_CLK
differential pair D_USB1_D: +USB1_DP -USB1_DM
differential pair D_USB0_D: +USB0_DP -USB0_DM

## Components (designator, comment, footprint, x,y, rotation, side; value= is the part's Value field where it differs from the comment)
C1 "10uF, 10V" 805 26170,13438.62 r0 top locked
C2 "10uF, 10V" 805 26202,13601 r270 top locked
C3 "0.1uf, 6V3" 402 26327,13796 r270 top locked
C4 "10uF, 10V" 805 26335,13799 r270 bottom locked
C5 "100uF" 7343T 24792.44,13158.59 r0 bottom locked
C6 "0.1uF" 402 27695,11708.62 r0 bottom locked
C7 "10uF, 10V" 805 26610.12,13400.57 r180 bottom locked
C8 "10uF, 10V" 805 26452.44,13433.94 r0 bottom locked
C9 "10uF, 10V" 805 26485.12,13249.6 r0 bottom locked
C10 "10uF, 10V" 805 26602,13550 r90 bottom locked
C11 "10uF, 10V" 805 26739,13652 r270 bottom locked
C12 "10uF, 10V" 805 26828,13312 r180 top locked
C13 "10uF, 10V" 805 26567,13661 r180 bottom locked
C14 "10uF, 10V" 805 26637,13791 r180 top locked
C15 "10uF, 10V" 805 26472,13791 r180 top locked
C16 "2.2uF, 6V3" 0805 26203.4,13836 r0 bottom locked
C17 "2.2uF, 6V3" 0805 26544.54,13977.88 r0 bottom locked
C18 "2.2uF, 6V3" 0805 26060.86,13836.62 r180 bottom locked
C19 "470pF, 50V" 402 26399.54,13977.88 r270 bottom locked
C20 "0.1uf, 6V3" 402 26449.54,13977.88 r270 bottom locked
C21 "18pF, 50V" 402 26427,12802.11 r180 top locked
C22 "18pF, 50V" 402 26342,12802.11 r0 top locked
C23 "10uF/10V/0805" "3528T/CASE B" 26595,11573.62 r180 bottom locked
C24 "1uF, 10V" 402 26903.73,13840 r270 top locked
C25 "18pF, 50V" 402 26495.12,11880.04 r180 top locked
C26 "18pF, 50V" 402 26580.12,11880.04 r0 top locked
C27 "0.1uf, 6V3" 402 27270,12965 r270 top
C28 "0.1uf, 6V3" 402 26101,12480 r180 bottom locked
C29 "0.1uf, 6V3" 402 26856.27,14002 r90 bottom locked
C30 "0.1uf, 6V3" 402 27335,14055 r0 top locked
C31 "0.1uf, 6V3" 402 26685,13047 r90 top locked
C32 "1nF, 50V" 402 26593.5,13047 r90 top locked
C33 "0.1uf, 6V3" 402 26639.25,13047 r90 top locked
C34 "100uF" 7343T 28055.12,11695.57 r0 bottom locked
C35 "0.1uf, 6V3" 402 27947.7,12032.36 r0 top locked
C36 "0.1uf, 6V3" 402 28121,11533.62 r90 top locked
C37 "0.1uf, 6V3" 402 26805,12385 r0 bottom locked
C38 "0.1uf, 6V3" 402 26389,12203 r0 bottom locked
C39 "10uF, 10V" 805 26914,13000 r270 bottom locked
C40 "10uF, 10V" 805 26760,13000 r270 bottom locked
C41 "0.1uf, 6V3" 402 26853.02,12866 r270 bottom locked
C42 "0.1uf, 6V3" 402 26893.02,12866 r270 bottom locked
C43 "0.1uf, 6V3" 402 26456.98,12364 r180 bottom locked
C44 "0.1uf, 6V3" 402 26442.48,12301.02 r180 bottom locked
C45 "0.1uf, 6V3" 402 26758.02,12866 r270 bottom locked
C46 "0.1uf, 6V3" 402 26798.02,12866 r270 bottom locked
C47 "0.1uf, 6V3" 402 26521.98,12399 r270 bottom locked
C48 "0.1uf, 6V3" 402 26800,12865 r270 top locked
C49 "0.1uf, 6V3" 402 26586.98,12364 r180 bottom locked
C50 "0.1uf, 6V3" 402 26521.98,12314 r90 bottom locked
C51 "0.1uf, 6V3" 402 26584,12280 r90 bottom locked
C52 "0.1uf, 6V3" 402 26521.98,12229 r270 bottom locked
C53 "0.1uf, 6V3" 402 26758.02,12865 r270 top locked
C54 "0.1uf, 6V3" 402 26855,12865 r270 top locked
C55 "10uF, 10V" 805 26837,13000 r270 bottom locked
C56 "0.1uf, 6V3" 402 26443,12241 r180 bottom locked
C57 "0.1uf, 6V3" 402 26510,12055 r90 bottom locked
C58 "0.1uf, 6V3" 402 26366,12286 r90 bottom locked
C59 "0.1uf, 6V3" 402 26740,12645 r90 bottom locked
C60 "0.1uf, 6V3" 402 26700,12645 r270 bottom locked
C61 "0.1uf, 6V3" 402 26835,12645 r270 bottom locked
C62 "10uF, 10V" 805 26759.06,13170.61 r180 bottom locked
C63 "0.1uf, 6V3" 402 26805,12305 r0 bottom locked
C64 "0.1uf, 6V3" 402 26521.98,12484 r90 bottom locked
C65 "0.1uf, 6V3" 402 26655.96,12489 r0 bottom locked
C66 "0.1uf, 6V3" 402 26805,12345 r0 bottom locked
C67 "0.1uf, 6V3" 402 26550,12055 r270 bottom locked
C68 "0.1uf, 6V3" 402 26470,12055 r90 bottom locked
C69 "0.1uf, 6V3" 402 25170,12685 r180 bottom locked
C70 "0.1uf, 6V3" 402 26584.97,12482.98 r90 bottom locked
C71 "0.1uf, 6V3" 402 26430,12055 r90 bottom locked
C72 "0.1uf, 6V3" 402 27106.2,13033 r90 bottom locked
C73 "0.1uf, 6V3" 402 27151.4,13033 r90 bottom locked
C74 "0.1uf, 6V3" 402 26805,12425 r180 bottom locked
C75 "0.1uf, 6V3" 402 26780,12645 r270 bottom locked
C76 "0.1uf, 6V3" 402 26805,12465 r180 bottom locked
C77 "10uF, 10V" 805 26887.42,12382.42 r90 bottom locked
C78 "0.1uf, 6V3" 402 26663.98,12204 r180 bottom locked
C79 "0.1uf, 6V3" 402 26584.97,12191.53 r90 bottom locked
C80 "0.1uf, 6V3" 402 26842,12244 r0 bottom locked
C81 "0.1uf, 6V3" 402 26310,12650 r180 bottom locked
C82 "0.1uf, 6V3" 402 26620,12645 r90 bottom locked
C83 "0.1uf, 6V3" 402 26842,12154 r0 bottom locked
C84 "0.1uf, 6V3" 402 26842,12199 r0 bottom locked
C85 "0.1uf, 6V3" 402 26664,12307 r0 bottom locked
C86 "0.1uf, 6V3" 402 26695.45,12264.52 r180 bottom locked
C87 "0.1uf, 6V3" 402 25170,12640 r0 bottom locked
C88 "0.1uf, 6V3" 402 26932.38,12249 r0 bottom locked
C89 "1uF, 10V" 402 26450.54,12715 r90 bottom locked
C90 "1uF, 10V" 402 26695.12,12955.57 r90 bottom locked
C91 "1uF, 10V" 402 26660,12645 r90 bottom locked
C92 "0.1uf, 6V3" 402 26655.96,12426.99 r180 bottom locked
C93 "0.1uf, 6V3" 402 26500,13050 r270 top locked
C94 "0.1uf, 6V3" 402 26458.99,12474.28 r270 bottom locked
C95 "10uF, 10V" 805 25488.74,12505 r90 bottom locked
C96 "10uF, 10V" 805 25488.74,12675 r270 top locked
C97 "0.1uf, 6V3" 402 25600,12710 r90 bottom locked
C98 "0.1uf, 6V3" 402 25600,12350 r270 bottom locked
C99 "0.1uf, 6V3" 402 26392.49,12426.99 r0 bottom locked
C100 "0.1uf, 6V3" 402 26392,12487 r0 bottom locked
C101 "0.1uf, 6V3" 402 25914,12440 r0 bottom locked
C102 "0.1uf, 6V3" 402 25600,12445 r90 bottom locked
C103 "0.1uf, 6V3" 402 26371.98,12364 r0 bottom locked
C104 "1uF, 10V" 402 26410,12715 r90 bottom locked
C105 "0.1uf, 6V3" 402 26411.74,12650 r180 bottom locked
C106 "0.1uf, 6V3" 402 26145,13065 r270 top locked
C107 "0.1uf, 6V3" 402 25690,12240 r180 bottom locked
C108 "0.1uf, 6V3" 402 25640,12535 r90 bottom locked
C109 "0.1uf, 6V3" 402 25997,12309 r90 bottom locked
C110 "0.1uf, 6V3" 402 25997,12674 r270 bottom locked
C111 "0.1uf, 6V3" 402 26034,12458 r90 bottom locked
C112 "0.1uf, 6V3" 402 26016,12594 r0 bottom locked
C113 "0.1uf, 6V3" 402 25640,12710 r90 bottom locked
C114 "0.1uf, 6V3" 402 25914,12479 r0 bottom locked
C115 "0.1uf, 6V3" 402 26042,12309 r90 bottom locked
C116 "0.1uf, 6V3" 402 25640,12445 r90 bottom locked
C117 "0.1uf, 6V3" 402 25917,12539 r0 bottom locked
C118 "10uF, 10V" 805 25488.74,12505 r90 top locked
C119 "0.1uf, 6V3" 402 25630,12800 r90 bottom locked
C120 "0.1uf, 6V3" 402 25640,12350 r270 bottom locked
C121 "0.1uf, 6V3" 402 25991.08,12458 r90 bottom locked
C122 "10uF, 10V" 805 25488.74,12675 r270 bottom locked
C123 "1nF, 50V" 402 25817,12653.97 r0 bottom locked
C124 "0.1uf, 6V3" 402 25817,12608.97 r0 bottom locked
C125 "0.1uF" 402 26540,11573.62 r180 top locked
C126 "10uF, 10V" 805 27236.62,13280.57 r180 bottom locked
C127 "0.01uf, 6V3" 402 27196,13197 r0 bottom locked
C128 "0.1uf, 6V3" 402 27340.2,13206 r270 bottom locked
C129 "0.1uf, 6V3" 402 27355,13385.4 r90 bottom locked
C130 "0.1uf, 6V3" 402 27380.2,13206 r90 bottom locked
C131 "0.1uf, 6V3" 402 27452.06,12574 r180 bottom locked
C132 "0.1uf, 6V3" 402 27502.11,12459.45 r90 bottom locked
C133 "10uF, 10V" 805 27625,12329 r0 top locked
C134 "1uF, 10V" 402 27353.11,12574 r180 bottom locked
C135 "0.1uf, 6V3" 402 27304.11,12459.15 r270 bottom locked
C136 "470pF, 50V" 402 27353.11,12534 r180 bottom locked
C137 "15pF, DNI" 402 28175,12218.62 r180 bottom locked
C138 "15pF, DNI" 402 28175,12172.8 r180 bottom locked
C139 "15pF, DNI" 402 28175,12308.62 r180 bottom locked
C140 "15pF, DNI" 402 28175,12265 r180 bottom locked
C141 "0.022uF,10V" 402 27765,12594 r270 bottom locked
C142 "30pF, 50V" 402 27489.3,12753.4 r0 top locked
C143 "30pF, 50V" 402 27404.3,12753.4 r180 top locked
C144 "0.1uf, 6V3" 402 27355,13295 r90 bottom locked
C145 "0.1uf, 6V3" 402 26900,14000 r270 top locked
C146 "0.1uf, 6V3" 402 27112,12090.88 r270 bottom
C147 "EEE-FK1A220R" 7343T 27670.12,10825.57 r180 bottom locked
C148 "0.1uf, 6V3" 402 27210,13930 r180 top locked
C149 "16SVP180M" 7343T 27370,11298.62 r90 bottom locked
C150 "10uF, 10V" 805 27717,13217 r270 bottom locked
C151 "0.01uf, 6V3" 402 27657,13212 r90 bottom locked
C152 "0.1uf, 6V3" 402 27060,12645 r90 bottom locked
C153 "10uF, 10V" 805 27566,13914.15 r180 top locked
C154 "0.1uf, 6V3" 402 27566,13854.15 r180 top locked
C155 "0.1uf, 6V3" 402 27792.62,13853.57 r270 bottom locked
C156 "47pF, 6.3V" 402 26352.09,11357.56 r180 bottom locked
C157 "47pF, 6.3V" 402 26252.09,11357.56 r180 bottom locked
C158 "0.1uf, 6V3" 402 27820.2,13206 r270 bottom locked
C159 "0.1uf, 6V3" 402 26960,13200 r90 top locked
C160 "47pF, 6.3V" 402 26252.09,11357.56 r180 top locked
C161 "47pF, 6.3V" 402 26146.19,11358.94 r180 bottom locked
C162 "47pF, 6.3V" 402 26146.19,11358.94 r180 top locked
C163 "47pF, 6.3V" 402 26041.19,11358.94 r180 bottom locked
C164 "47pF, 6.3V" 402 26552.09,11357.56 r180 bottom locked
C165 "47pF, 6.3V" 402 26552.09,11357.56 r180 top locked
C166 "47pF, 6.3V" 402 26452.09,11357.56 r180 top locked
C167 "47pF, 6.3V" 402 26352.09,11357.56 r180 top locked
C168 "47pF, 6.3V" 402 26452.09,11357.56 r180 bottom locked
C169 "47pF, 6.3V" 402 26041.19,11358.94 r180 top locked
C170 "47pF, 6.3V" 402 25941.19,11358.94 r180 bottom locked
C171 "47pF, 6.3V" 402 25841.19,11358.94 r180 bottom locked
C172 "47pF, 6.3V" 402 25941.19,11358.94 r180 top locked
C173 "47pF, 6.3V" 402 25841.19,11358.94 r180 top locked
C174 "0.1uf, 6V3" 402 27835,13385.4 r90 bottom locked
C175 "0.1uf, 6V3" 402 27860.2,13206 r90 bottom locked
C176 "0.1uf, 6V3" 402 27835,13295 r90 bottom locked
C177 "47uF,1206" 1206 24672,14125.62 r0 top locked
C178 "47uF,1206" 1206 24872,14125.62 r180 top locked
C179 "0.1uf, 6V3,DNI" 402 25102,13980.62 r0 top locked
C180 "0.1uf, 6V3" 402 24632.63,13953.62 r270 top locked
C181 "10uF, 10V" 805 24562.63,13948.62 r270 top locked
C182 "0.1uf, 6V3,DNI" 402 25077,14005.62 r270 bottom locked
C183 "0.1uf, 6V3,DNI" 402 25102,13800.62 r0 top locked
C184 "0.1uf, 6V3,DNI" 402 25102,13890.62 r0 top locked
C185 "0.1uf, 6V3" 402 24907,14015.62 r0 bottom locked
C186 "10uF, 10V" 805 24912,14110.62 r180 bottom locked
C187 "0.1uf, 6V3" 402 24777,14015.62 r0 bottom locked
C188 "10uF, 10V" 805 24767,14110.62 r180 bottom locked
C189 "0.1uf, 6V3" 402 24954.79,13542.83 r180 top locked
C190 "10uF, 10V" 805 24955,13480.57 r0 top locked
C191 "0.1uf, 6V3" 402 24629.73,13626.35 r270 top locked
C192 "10uF, 10V" 805 24564.73,13626.35 r90 top locked
C193 "0.1uf, 6V3,DNI" 402 25102,13935.62 r0 top locked
C194 "0.01uf, 6V3,DNI" 402 25102,13845.62 r0 top locked
C195 "10uF" 3528T 25425,13285 r270 top locked
C196 "100uF" 7343T 25935.12,13245.57 r270 top locked
C197 "10uF" 3528T 25270,13800 r90 bottom locked
C198 "100uF" 7343T 25770,13800 r90 bottom locked
C199 "C1005X5R0J104K" 0805 28040.12,10885.57 r0 bottom locked
C200 "2.2uF, 6V3" 0805 25160,12550 r270 bottom locked
C201 "470pF, 50V" 402 25050,12410 r180 bottom locked
C202 "0.1uf, 6V3" 402 24980,12440 r270 top locked
C203 "GRM216R71H103KA01D" 0805 27555.12,11045.57 r180 bottom locked
C204 "4.7uF, 10V" 805 24915,12445 r90 top locked
C205 "4.7uF, 10V" 805 24791,12410 r180 top locked
C206 "4.7uF, 10V" 805 24155,12225 r0 bottom locked
C207 "0.1uf, 6V3" 402 26193.28,11177.95 r90 top locked
C208 "0.1uf, 6V3" 402 25585.37,11638 r180 bottom locked
C209 "0.1uf, 6V3" 402 25314,12098 r0 bottom locked
C210 "0.1uf, 6V3" 402 25314,12058 r0 bottom locked
C211 "0.1uf, 6V3" 402 26354,11156.62 r0 top locked
C212 "0.1uf, 6V3" 402 24790,12660 r0 top locked
C213 "0.1uf, 6V3" 402 25585,11595 r180 bottom locked
C214 "0.1uf, 6V3" 402 25463,11830 r0 bottom locked
C215 "0.1uf, 6V3" 402 24790,12660 r0 bottom locked
C216 "0.1uf, 6V3" 402 25570.72,11136.73 r180 top locked
C217 "0.1uf, 6V3" 402 25463,11877 r0 bottom locked
C218 "0.1uf, 6V3" 402 25390.12,11635.57 r0 bottom locked
C219 "0.1uf, 6V3" 402 25570.72,11087.73 r180 top locked
C220 "33pF" 402 26151,11739 r0 top locked
C221 "33pF" 402 26151,11694 r0 top locked
C222 "33pF" 402 26151,11649 r0 top locked
C223 "33pF" 402 26151,11604 r0 top locked
C224 "33pF" 402 25755,11288.62 r90 bottom locked
C225 "33pF" 402 25709.24,11288.62 r90 bottom locked
C226 "33pF" 402 25663.47,11288.62 r90 bottom locked
C227 "33pF" 402 25617.71,11288.62 r90 bottom locked
C228 "33pF" 402 25567.24,11288.62 r90 bottom locked
C229 "33pF" 402 25521.48,11288.62 r90 bottom locked
C230 "0.1uf, 6V3" 402 25390.12,11680.57 r0 bottom locked
C231 "0.1uf, 6V3" 402 26261,11155.62 r180 top locked
C232 "0.1uf, 6V3" 402 26421,11180.62 r90 top locked
C233 "33pF" 402 25475.71,11288.62 r90 bottom locked
C234 "33pF" 402 25429.95,11288.62 r90 bottom locked
C235 "33pF" 402 25379.53,11288.62 r90 bottom locked
C236 "33pF" 402 25333.76,11288.62 r90 bottom locked
C237 "33pF" 402 25288,11288.62 r90 bottom locked
C238 "33pF" 402 25242.24,11288.62 r90 bottom locked
C239 "33pF" 402 25197.97,11288.62 r90 bottom locked
C240 "33pF" 402 25152.2,11288.62 r90 bottom locked
C241 "0.1uf, 6V3" 402 24537.94,12791.39 r90 bottom locked
C242 "4.7uF, 10V" 805 24386,12982 r0 top locked
C243 "4.7uF, 10V" 805 24385,13060 r0 top locked
C244 "NC" 805 24386,12905 r0 top locked
C245 "4.7uF, 35V" 1210 24485,11708.19 r270 top locked
C246 "4.7uF, 35V" 1210 24350,11703.19 r270 top locked
C247 "1uF, 10V" 0805 24400,12025 r270 bottom locked
C248 "1uF, 10V" 0805 24320,12025 r270 bottom locked
C249 "0.1uf, 6V3" 402 24530.2,12699.61 r180 bottom locked
C250 "1uF, 10V" 0805 24829,12250 r180 top locked
C251 "4.7uF, 35V" 1210 24445,12192.87 r270 top locked
C252 "4.7uF, 35V" 1210 24580,12192.87 r270 top locked
C253 "4.7uF, 35V" 1210 24580,12192.87 r270 bottom locked
C254 "4.7uF, 35V" 1210 24445,12192.87 r270 bottom locked
C255 "0.1uf, 6V3" 402 24502,12030 r90 bottom locked
C256 "100pF" 402 24760,12740 r270 bottom locked
C257 "3300pF" C0603 24840,12740 r270 bottom locked
C258 "0.1uf, 6V3" 402 24502,12030 r270 top locked
C259 "1uF, 10V" 0805 24732,12944 r0 top locked
C260 "1uF, 10V" 0805 24160,11360 r90 bottom locked
C261 "4.7uF, 10V" 805 24160,11677 r270 bottom locked
C262 "Cap Pol1" "6032/CASE C" 24270,12360 r180 bottom locked
C263 "Cap Pol1" "6032/CASE C" 24780,12500 r0 bottom locked
C264 "0.1uf, 6V3" 402 24630,12459 r90 top locked
C265 "0.1uf, 6V3" 402 24545,12599 r90 top locked
C266 "0.1uf, 6V3" 402 24530,12360 r0 top locked
C267 "0.1uf, 6V3" 402 24420,12589 r0 top locked
C268 "0.1uf, 6V3" 402 24355,12472 r90 bottom locked
C269 "0.1uf, 6V3" 402 24420,12634 r0 top locked
C270 "0.1uf, 6V3" 402 24305,12472 r90 bottom locked
C271 "0.1uf, 6V3" 402 24205,12475 r0 bottom locked
C272 "0.1uf, 6V3" 402 24460,12030 r90 bottom locked
C273 "0.1uf, 6V3" 402 24465,11763 r270 bottom locked
C274 "0.1uf, 6V3" 402 24460,12030 r90 top locked
C275 "0.1uf, 6V3" 402 24420,11763 r270 bottom locked
C276 "0.1uf, 6V3" 402 24315,12020 r90 top locked
C277 "0.1uf, 6V3" 402 24205,11840 r180 bottom locked
C281 "CC0805KRX7R9BB561" 0805 27555.97,10964.4 r180 bottom locked
C282 "GRM216R71H103KA01D" 0805 28205.12,11275.57 r180 bottom locked
D1 "598-8170-107F" LED_0603 26065.86,13838.62 r0 top locked
D2 "598-8170-107F" LED_0603 25978.19,13995.72 r270 top locked
D3 "598-8170-107F" LED_0603 26058.19,13995.72 r270 top locked
D4 "598-8170-107F" LED_0603 26138.19,13995.72 r270 top locked
D5 "598-8170-107F" LED_0603 26218.19,13995.72 r270 top locked
D6 "Diode" DSO-C2/X3.3 27830,11268.62 r180 bottom locked
D7 "RB501-40V" DSO-C2/X2.3 24309,12301 r90 top locked
D8 "RB501-40V" DSO-C2/X2.3 24175,12305 r270 top locked
D9 "RB501-40V" DSO-C2/X2.3 24190,11955 r270 top locked
D10 "RB501-40V" DSO-C2/X2.3 24280,11351.5 r180 top locked
D11 "RB501-40V" DSO-C2/X2.3 24270,11525 r0 top locked
Designator303 "Comment" FPC-MARKS#1 24952.53,14587.2 r0 top
Designator303_1 "Comment" FPC-MARKS#1 24952.53,10453.35 r0 top
Designator303_1_1 "Comment" FPC-MARKS#1 27672.6,10453.35 r0 top
Designator303_2 "Comment" FPC-MARKS#1 24494.06,14270.61 r0 top
Designator303_3 "Comment" FPC-MARKS#1 28094.06,14320.61 r0 top
Designator303_4 "Comment" FPC-MARKS#1 24574.06,10730.61 r0 top
Designator304 "Comment" FPC-MARKS#2 24952.53,14587.2 r180 bottom
Designator304_1 "Comment" FPC-MARKS#2 24952.53,10453.35 r180 bottom
Designator304_1_1 "Comment" FPC-MARKS#2 27672.6,10453.35 r180 bottom
Designator304_2 "Comment" FPC-MARKS#2 24494.06,14270.61 r180 bottom
Designator304_3 "Comment" FPC-MARKS#2 28094.06,14320.61 r180 bottom
Designator304_4 "Comment" FPC-MARKS#2 24574.06,10730.61 r180 bottom
Designator316 "Comment" FPC-MARKS#1 27255.12,12210.57 r180 top
Designator317 "Comment" FPC-MARKS#1 27730,12935 r180 top
Designator319 "Comment" FPC-MARKS#1 25157.33,12289.01 r180 top
Designator320 "Comment" FPC-MARKS#1 25822.43,11520.53 r180 top
FB1 "150OHM800mA" SM-7351-IND-0805 26220,13065 r270 top locked
FB2 "150OHM800mA" SM-7351-IND-0805 26344,13066 r90 top locked
FB3 "150OHM800mA" SM-7351-IND-0805 26600,13050 r180 bottom locked
FB4 "150OHM800mA" SM-7351-IND-0805 27625,12239 r180 top locked
FB5 "0.1OHM1A" SM-7351-IND-0805 25263.62,13357.47 r90 bottom locked
FB6 "0.1OHM1A" SM-7351-IND-0805 24574.12,13922.17 r90 bottom locked
FB7 "150OHM800mA" SM-7351-IND-0805 27968,12175.05 r270 bottom locked
FB8 "0.1 Ohm, 0805" SM-7351-IND-0805 27872.5,12177.05 r90 bottom locked
FB9 "0.1OHM1A" SM-7351-IND-0805 25123.22,14166.07 r180 top locked
FB10 "0.1 Ohm, 0805,DNI" SM-7351-IND-0805 24455.12,10865.57 r0 top locked
FB11 "0.1 Ohm, 0805,DNI" SM-7351-IND-0805 28162.53,14170.57 r180 bottom locked
FB12 "0.1OHM1A" SM-7351-IND-0805 24791,12593 r0 top locked
FB13 "0.1OHM1A" SM-7351-IND-0805 24791,12500 r0 top locked
FB14 "0.1OHM1A" SM-7351-IND-0805 24345,11512 r90 bottom locked
FB15 "0.1OHM1A" SM-7351-IND-0805 24297.4,12225 r0 bottom locked
FB16 "0.1OHM1A" SM-7351-IND-0805 24241,11514 r90 bottom locked
FB17 "0.1OHM1A,DNI" SM-7351-IND-0805 28040,10793.62 r0 bottom locked
J1 "Header 3" HDR1X3 27485.12,14180.57 r0 top locked
J2 "JACK_BACKLIGHT" JACK_BACKLIGHT 26995,11298.62 r270 bottom locked
L1 "2.2uH, 2.6A" 2520 26487.06,13312 r0 top locked
L2 "2.2uH, 2.6A" 2520 26667.06,13312 r180 top locked
L3 "2.2uH, 2.6A" 2520 26739,13652 r90 top locked
L4 "220uH" L330 27390,11313.62 r0 top locked
L5 "10uH" 2520 24565,12946 r180 top locked
LS1 "Speaker" PIN2 24210,12978 r90 bottom locked
M1 "CSD17308Q3" MOSFET_Q3 28206.98,11081.86 r0 bottom locked
MTG1 "MHOLE" MTGH200C125D_PL 28462.21,14172.66 r0 top locked
MTG2 "MHOLE" MTGH200C125D_PL 28462.21,10865.57 r0 top locked
MTG3 "MHOLE" MTGH200C125D_PL 24155.12,10865.57 r0 top locked
MTG4 "MHOLE" MTGH200C125D_PL 24155.12,14172.66 r0 top locked
P4 "mini USB-B" USB5MINI_4SHIELDED_SMD-5 28452,11508.62 r0 bottom locked
P6 "HDR_14X2" HDR_14X2 28400.94,12520.28 r270 top locked
P9 "HDR_2X1" HDR_2X1 27995.12,10675.57 r180 top locked
P10 "MOLEX 502570-001" SD-MICRO-SCHA5B0300 28279.43,13665.89 r90 bottom locked
P11 "Header 3" HDR1X3 27308.26,13550 r180 top locked
P12 "Header 3" HDR1X3 27308.26,13663 r180 bottom locked
P13 "Header 3" HDR1X3 27657,13550 r180 top locked
P15 "Header 3" HDR1X3 27657,13661 r180 bottom locked
P16 "SJ3524-3.5mm" JACK_AUDIO1 24193.52,13753.89 r180 top locked (schematic designator P14)
P17 "SJ3524-3.5mm" JACK_AUDIO1 24193.52,13373.62 r180 top locked (schematic designator P14)
P18 "FPC_CON_30X2" FPC_CON_30X2 26311.65,10978.27 r180 bottom locked
P19 "Header 3" HDR1X3 27565,13020 r180 bottom locked
Q1 "DMC56404" SMINI6-F3-B 26006.19,14123.22 r270 top locked
Q2 "DMC56404" SMINI6-F3-B 26198.19,14122.59 r270 top locked
Q3 "DMC56404" SMINI6-F3-B 24110.19,13022.07 r180 top locked
R1 "100K, 1%" R0402 26377,13791 r270 top locked
R2 "4.7k, 1%" R0402 27690,11613.62 r0 bottom locked
R3 "1.5K, 1%" R0402 26757,13526 r180 bottom locked
R4 "1.5K, 1%" R0402 26757,13481 r180 bottom locked
R5 "0R, 1%" R0402 26255.86,13771 r180 bottom locked
R6 "0R, 1%" R0402 26491.27,13160 r0 bottom locked
R7 "0R, 1%" R0402 26255.86,13771 r180 top locked
R8 "0R, 1%" R0402 26255.86,13816 r180 top locked
R9 "0R, 1%, DNI" R0402 26637,13796 r180 bottom locked
R10 "470K, 5%" R0402 26349.54,13977.88 r270 bottom locked
R11 "280K, 1%" R0402 26425.92,13992.88 r180 top locked
R12 "820, 5%" R0402 25945,13838.62 r0 top locked
R13 "4.7k, 1%" R0402 27690,11898.62 r0 bottom locked
R14 "10K, 1%" R0402 26855.73,13845 r90 top locked
R15 "4.7k, 1%" R0402 27690,11948.62 r0 bottom locked
R16 "4.7k, 1%" R0402 27690,11753.62 r0 bottom locked
R17 "1M, 1%" R0402 26531.72,11836.62 r0 top locked
R18 "33, 0402" R0402 27105.2,12900 r90 bottom locked
R19 "0R, 1%" R0402 26806.14,12517 r0 bottom locked
R20 "0R, 1%" R0402 26806.14,12557 r180 bottom locked
R21 "33, 0402" R0402 27197,13034 r270 bottom locked
R22 "49.9, 1%" R0402 26240,12385 r0 bottom locked
R23 "4.75K, 1%" R0402 27245,14055 r0 top locked
R24 "4.75K, 1%" R0402 27335,14010 r180 top locked
R25 "4.75K, 1%" R0402 26855.12,13845.57 r90 bottom locked
R26 "4.75K, 1%" R0402 26410,12610 r180 bottom locked
R27 "0R, 1%" R0402 26545,13050 r270 top locked
R28 "33, 0402" R0402 27038.86,12449.24 r0 top locked
R29 "4.7k, 1%" R0402 27690,11802.38 r0 bottom locked
R30 "4.7k, 1%" R0402 27690,11663.62 r0 bottom locked
R31 "4.7k, 1%" R0402 27690,11850.29 r0 bottom locked
R32 "510R, 1%" R0402 24210,12975 r270 top locked
R33 "0R, 1%" R0603 27079.93,13225 r180 bottom locked
R34 "100K, 1%" R0402 24111.19,12915.07 r180 top locked
R35 "121, 1%" R0402 25770,13755.13 r90 top locked
R36 "54, 1%" R0402 25770,13830.13 r90 top locked
R37 "10k, 1%" R0402 26855,14000 r90 top locked
R38 "10k, 1%" R0402 27157,12089.74 r90 bottom
R39 "CRCW04021K00FKED" R0603 27587.25,11150.57 r270 bottom locked
R40 "10k, 1%" R0402 27245,14010 r180 top locked
R41 "CRCW04027K68FKED" R0603 27522.25,11150.57 r270 bottom locked
R42 "0R, 1%" R0603 27559.2,13219.06 r0 bottom locked
R43 "0R, 1%" R0402 24579,13418.62 r90 bottom locked
R44 "0R, 1%" R0402 24599,13809.41 r0 top locked
R45 "33, 0402" R0402 26270,11892 r180 bottom locked
R46 "33, 0402" R0402 26150,11805 r180 top locked
R47 "33, 0402" R0402 26150,11805 r180 bottom locked
R48 "33, 0402" R0402 26150,11670 r180 bottom locked
R49 "0R, 1%" R0402 26927.71,12190.18 r180 bottom locked
R50 "0R, 1%" R0402 26937,12866.86 r270 top locked
R51 "0R, 1%" R0402 26937,12866.86 r270 bottom locked
R52 "10k, 1%" R0402 27775.12,11993.07 r0 top locked
R53 "10k, 1%" R0402 27810.12,11735.57 r270 bottom locked
R54 "10k, 1%" R0402 26305,12695 r0 bottom locked
R55 "100K, 1%, DNI" R0402 26552.09,11267.56 r0 bottom locked
R56 "100K, 1%" R0402 26552.09,11267.56 r0 top locked
R57 "100K, 1%, DNI" R0402 26452.09,11267.56 r0 top locked
R58 "100K, 1%,DNI" R0402 26352.09,11267.56 r0 top locked
R59 "100K, 1%, DNI" R0402 26452.09,11267.56 r0 bottom locked
R60 "100K, 1%,DNI" R0402 26352.09,11267.56 r0 bottom locked
R61 "100K, 1%,DNI" R0402 26252.09,11267.56 r0 bottom locked
R62 "100K, 1%,DNI" R0402 26252.09,11267.56 r0 top locked
R63 "100K, 1%,DNI" R0402 26146.19,11268.94 r0 bottom locked
R64 "100K, 1%,DNI" R0402 26146.19,11268.94 r0 top locked
R65 "100K, 1%" R0402 26041.19,11268.94 r0 bottom locked
R66 "100K, 1%" R0402 26041.19,11268.94 r0 top locked
R67 "100K, 1%" R0402 25941.19,11268.94 r0 bottom locked
R68 "100K, 1%" R0402 25941.19,11268.94 r0 top locked
R69 "100K, 1%, DNI" R0402 25841.19,11268.94 r0 bottom locked
R70 "100K, 1%,DNI" R0402 25841.19,11268.94 r0 top locked
R71 "820, 5%" R0402 26218.19,13990.72 r270 bottom locked
R72 "820, 5%" R0402 25978.19,13990.72 r270 bottom locked
R73 "820, 5%" R0402 26058.19,13990.72 r270 bottom locked
R74 "820, 5%" R0402 26138.19,13990.72 r270 bottom locked
R75 "100" R0402 25972,11478.62 r90 top locked
R76 "100K, 1%" R0402 26035.72,14123.22 r270 bottom locked
R77 "100K, 1%" R0402 25976.67,14123.22 r90 bottom locked
R78 "100K, 1%" R0402 26227.72,14122.59 r270 bottom locked
R79 "100K, 1%" R0402 26168.67,14122.59 r90 bottom locked
R80 "100K, 1%" R0402 26552.09,11312.56 r180 bottom locked
R81 "100K, 1%, DNI" R0402 26552.09,11312.56 r180 top locked
R82 "100K, 1%" R0402 26452.09,11312.56 r180 top locked
R83 "100K, 1%" R0402 26352.09,11312.56 r180 top locked
R84 "100K, 1%" R0402 26452.09,11312.56 r180 bottom locked
R85 "100K, 1%" R0402 26352.09,11312.56 r180 bottom locked
R86 "100K, 1%" R0402 26252.09,11312.56 r180 bottom locked
R87 "100K, 1%" R0402 26252.09,11312.56 r180 top locked
R88 "100K, 1%" R0402 26146.19,11313.94 r180 bottom locked
R89 "100K, 1%" R0402 26146.19,11313.94 r180 top locked
R90 "100K, 1%, DNI" R0402 26041.19,11313.94 r180 bottom locked
R91 "100K, 1%, DNI" R0402 26041.19,11313.94 r180 top locked
R92 "100K, 1%, DNI" R0402 25941.19,11313.94 r180 bottom locked
R93 "100K, 1%, DNI" R0402 25941.19,11313.94 r180 top locked
R94 "100K, 1%" R0402 25841.19,11313.94 r180 bottom locked
R95 "100K, 1%" R0402 25841.19,11313.94 r180 top locked
R96 "10k, 1%" R0402 25622,12598.97 r0 bottom locked
R97 "1.5K, 1%" R0402 25997.23,12764 r90 bottom locked
R98 "10k, 1%" R0402 25820.86,12498.97 r0 bottom locked
R99 "240, 1%" R0402 25622,12643.97 r0 bottom locked
R100 "10k, 1%" R0402 25820.86,12543.97 r180 bottom locked
R101 "0R, 1%" R0402 24729,13468.62 r270 top locked
R102 "0R, 1%" R0402 24757.86,13553.62 r0 bottom locked
R103 "0R, 1%" R0402 24779,13468.62 r90 top locked
R104 "2.2K,1%" R0402 25102,14025.62 r0 top locked
R105 "330R, 1%" R0402 25190,14003.62 r270 bottom locked
R106 "0R, 1%" R0402 25102,13935.62 r0 bottom locked
R107 "0R, 1%" R0402 25102,13845.62 r0 bottom locked
R108 "0R, 1%" R0402 25102,13800.62 r180 bottom locked
R109 "0R, 1%" R0402 25102,13890.62 r180 bottom locked
R110 "0R, 1%" R0402 26665.12,11875.57 r0 top locked
R111 "0ohm, 1%" R0805 26150,11893.19 r0 bottom locked
R112 "1.5K, 1%" R0402 27188.86,12487.33 r180 bottom locked
R113 "1.5K, 1%" R0402 27188.86,12359.83 r180 bottom locked
R114 "1.5K, 1%" R0402 27188.86,12533.17 r180 bottom locked
R115 "10k, 1%" R0402 27188.86,12432 r180 bottom locked
R116 "10k, 1%" R0402 27253.11,12684 r90 bottom locked
R117 "10k, 1%" R0402 27188.86,12589 r180 bottom locked
R118 "10k, 1%" R0402 27297.4,12684 r90 bottom locked
R119 "1.5K, 1%" R0402 27188.86,12314 r0 top locked
R120 "49.9, 1%" R0402 27643.86,12562 r0 top locked
R121 "49.9, 1%" R0402 27643.86,12512 r0 top locked
R122 "49.9, 1%" R0402 27643.86,12467 r0 top locked
R123 "49.9, 1%" R0402 27643.86,12414 r0 top locked
R124 "10, 1%,DNI" R0402 27341.68,12684 r270 top locked
R125 "100, 1%" R0402 27253.11,12684 r270 top locked
R126 "100, 1%" R0402 27188.86,12589 r0 top locked
R127 "100, 1%" R0402 27188.86,12533.17 r0 top locked
R128 "100, 1%" R0402 27188.86,12487.33 r0 top locked
R129 "100, 1%" R0402 27585,12459 r270 bottom locked
R130 "470, 5%" R0402 27986.89,13000.26 r0 top locked
R131 "100, 1%" R0402 27297.4,12684 r270 top locked
R132 "470, 5%" R0402 27986.89,13050.26 r0 top locked
R133 "100, 1%" R0402 27188.86,12432 r0 top locked
R134 "100, 1%" R0402 27391.88,12280.06 r90 top locked
R135 "10k, 1%" R0402 27563.11,12684 r90 top locked
R137 "0R, 1%,DNI" R0402 27720,12594 r270 bottom locked
R138 "100, 1%" R0402 27188.86,12359.83 r0 top locked
R139 "100, 1%" R0402 27038.86,12493 r0 top locked
R140 "0R, 1%,DNI" R0402 27385.97,12684 r270 top locked
R141 "1M, 1%,DNI" R0402 27474.54,12684 r90 top locked
R142 "0R, 1%" R0402 27430.25,12684 r270 top locked
R143 "10, 1%" R0402 27518.82,12684 r90 top locked
R144 "12.1K, 1%" R0402 27643.86,12607 r0 top locked
R145 "10k, 1%" R0402 27349.22,12280.06 r270 top locked
R146 "NC" R0805 26161.02,10978.27 r180 top locked
R147 "200K,1%" R0805 26587.45,10978.27 r0 top locked
R148 "100ohm,1%" R0603 24829,11900 r180 bottom locked
R149 "470K, 5%" R0402 25050,12460 r180 bottom locked
R150 "10k, 1%" R0402 28359.43,13845.27 r90 top locked
R151 "10k, 1%" R0402 28454.43,13845.27 r90 top locked
R152 "10k, 1%" R0402 28454.12,13498.43 r270 top locked
R153 "10k, 1%" R0402 28404.12,13498.43 r270 top locked
R154 "10k, 1%" R0402 28354.12,13498.43 r270 top locked
R155 "10k, 1%" R0402 28406.71,13845.27 r90 top locked
R156 "10k, 1%" R0402 27100,12645 r90 bottom locked
R157 "10k, 1%" R0402 27890.12,13900.57 r180 top locked
R158 "10k, 1%" R0402 26837.33,12107.04 r180 bottom locked
R159 "0R, 1%" R0402 26927.71,12147.82 r180 bottom locked
R160 "0R, 1%" R0402 26929.06,12076.61 r0 bottom
R161 "280K, 1%" R0402 25050,12510 r0 bottom locked
R162 "20K,1%" R0805 24200,12055 r180 bottom locked
R163 "4.75K, 1%" R0402 26535,12716.14 r270 bottom locked
R164 "4.75K, 1%" R0402 26495,12716.14 r90 bottom locked
R165 "100K, 1%" R0402 27752.83,13926.57 r180 bottom locked
R166 "NC" R0603 24829,11900 r180 top locked
R167 "33, 0402" R0402 26729.06,13160.61 r180 top locked
R168 "CRCW0402100RFKED" R0603 28205.12,11202.38 r0 bottom
R169 "0ohm" R0805 26161.02,11059.16 r0 top locked
R170 "NC" R0805 26587.45,11059.16 r180 top locked
R171 "NC" R0603 24979.37,11823 r180 bottom locked
R172 "0R,1%" R0805 24200,11980 r0 bottom locked
R173 "CRCW040228K7FKED" R0603 28175.12,10950.57 r180 bottom locked
R174 "100ohm,1%" R0603 24979.37,11823 r180 top locked
R175 "CRCW040211K0FKED" R0603 27369.92,11028.62 r180 bottom locked
R176 "CSRN2010FK60L0" R2010 28195.12,11185.57 r270 top locked
R177 "100ohm,1%" R0603 24979,11895 r180 top locked
R178 "10K,1%" R0805 24155,12130 r180 bottom locked
R179 "NC" R0603 24979,11965 r180 bottom locked
R180 "100ohm,1%" R0603 24979,12105 r180 top locked
R181 "100ohm,1%" R0603 24979,11965 r180 top locked
R182 "100ohm,1%" R0603 24979,12105 r180 bottom locked
R183 "NC" R0805 24829,11748 r180 top locked
R184 "100ohm,1%" R0603 24979,12175 r180 top locked
R185 "NC" R0603 24829,11965 r180 top locked
R186 "NC" R0603 24979,12175 r180 bottom locked
R187 "0ohm, 1%" R0805 24829,11670 r0 top locked
R188 "100ohm,1%" R0603 24829,11965 r180 bottom locked
R189 "0ohm, 1%" R0805 25929.37,11970 r0 top locked
R190 "NC" R0805 24829,11748 r0 bottom locked
R191 "NC" R0805 25929.37,12045 r0 top locked
R192 "100ohm,1%" R0603 24829,12175 r180 top locked
R193 "10kohm, 1%" R0805 24829,12030 r0 bottom locked
R194 "10kohm, 1%" R0805 24829,12175 r0 bottom locked
R195 "100ohm,1%" R0603 24979,12035 r0 top locked
R196 "100ohm,1%" R0603 24829,12100 r180 top locked
R197 "100ohm,1%" R0603 24979,12035 r0 bottom locked
R198 "0ohm,DNI" R0805 24829,12032.5 r180 top
R199 "0ohm,DNI" R0805 24829,12100 r180 bottom locked
R200 "1K, 1%" R0805 24245,11675 r90 top locked
R201 "38K, 1%" R0805 24340,11711.06 r270 bottom locked
R202 "10kohm, 1%,DNI" R0805 24989,12250 r0 top locked
R203 "1kohm, 1%" R0805 24829,12250 r0 bottom locked
R204 "NC" R0805 24984,11670 r0 top locked
R205 "NC" R0805 24984.37,11748 r0 top locked
R206 "1kohm, 1%" R0805 24829,11825 r0 top locked
R207 "0ohm,1%" R0805 24989,12250 r180 bottom locked
R208 "1Kohm,1%" R0805 24984,11670 r180 bottom locked
R209 "1Kohm,1%" R0805 24984.37,11748 r180 bottom locked
R210 "NC" R0805 24829,11825 r180 bottom locked
R211 "38kohm, 1%" R0805 24801,12755 r0 top locked
R212 "68K, 1%" R0805 24681.81,12187.6 r270 bottom locked
R213 "NC" R0805 24386,12754 r0 top locked
R214 "10K, 1%" R0805 24681.81,12187.6 r90 top locked
R215 "0ohm, 1%" R0805 24386,12827 r0 top locked
R216 "0R, 1%" R0805 24160,11517 r90 bottom locked
R217 "68K, 1%" R0805 24160,11677 r270 top locked
R218 "0ohm,1%" R0805 24491.91,12502.37 r270 bottom locked
R219 "0ohm,1%" R0805 24165.63,12641.37 r270 bottom locked
R220 "0R,1%" R0805 24313,11887 r90 bottom locked
R221 "0ohm,1%" R0805 24244.72,12641.37 r270 top locked
R222 "2.7K,1%" R0805 24206.93,12535 r180 bottom locked
R223 "0ohm,1%" R0805 24300,12130 r0 bottom locked
R224 "0ohm,1%" R0805 24561,12502.37 r270 bottom locked
R225 "NC" R0805 24561,12477.37 r90 top locked
R226 "2.4K,1%" R0805 24491.91,12477.37 r270 top locked
R227 "NC" R0805 24440,12614 r180 bottom locked
R228 "2.7K,1%" R0805 24412.81,12502.37 r270 bottom locked
R229 "NC" R0805 24412.81,12477.37 r90 top locked
R230 "10K,1%" R0805 24244.72,12641.37 r270 bottom locked
R231 "2.4K,1%" R0805 24206.93,12535 r180 top locked
R232 "10K,1%" R0805 24165.63,12641.37 r90 top locked
R233 "NC" R0805 24480,11887.37 r270 bottom locked
R234 "2.7K,1%" R0805 24465,11892.37 r90 top locked
R235 "NC" R0805 24388,11892.37 r270 top locked
R236 "2.4K,1%" R0805 24398,11887.37 r90 bottom locked
R237 "NC" R0805 24313,11892 r270 top locked
R238 "0R,1%" R0805 24200,11905 r180 bottom locked
R239 "0R, 1%,1206,baoxian" R1206 26107,13625.06 r270 top locked
R240 "0R, 1%" R0603 27559.2,13282.87 r0 bottom locked
R241 "0R, 1%,1206,baoxian" R1206 24751.12,13166.57 r0 top locked
R242 "0R, 1%,DNI" R0603 27079.93,13287.87 r180 bottom locked
R243 "0R, 1%,DNI" R0603 27079.93,13348.87 r180 bottom locked
R244 "0R, 1%,DNI" R0603 27079.93,13410 r180 bottom locked
R245 "0R, 1%,DNI" R0603 27559.2,13343.87 r180 bottom locked
R246 "0R, 1%,DNI" R0603 27559.2,13410 r180 bottom locked
R247 "0R, 1%" R0603 28171.26,12883.62 r0 bottom locked
R248 "0R, 1%" R0603 28171.26,12948.62 r0 bottom locked
R249 "0R, 1%" R0603 28171.26,12753.62 r0 bottom locked
R250 "0R, 1%" R0603 28171.26,12818.62 r0 bottom locked
R251 "0R, 1%" R0603 28171.26,12558.62 r0 bottom locked
R252 "0R, 1%" R0603 28171.26,12493.62 r0 bottom locked
R253 "0R, 1%" R0603 28171.34,12688.62 r0 bottom locked
R254 "0R, 1%" R0603 26635,12032 r0 bottom locked
R255 "0R, 1%" R0603 28171.26,12428.62 r0 bottom locked
R256 "0R, 1%" R0603 28171.26,12363.62 r0 bottom locked
R259 "0R, 1%" R0603 26626.12,12845.57 r90 bottom locked
R260 "0R, 1%" R0603 28171.26,12623.62 r180 bottom locked
RA1 "15R,RES_ARRAY" R8_0603 25929,11846.5 r90 top locked
RA2 "15R,RES_ARRAY" R8_0603 25317,12244 r0 bottom locked
RA3 "15R,RES_ARRAY" R8_0603 25472.76,12245.63 r0 bottom locked
RA4 "15R,RES_ARRAY" R8_0603 25930,12006 r270 bottom locked
RA5 "15R,RES_ARRAY" R8_0603 25929,11846.5 r270 bottom locked
RA6 "15R,RES_ARRAY" R8_0603 25929,11667 r270 bottom locked
RA7 "33R,RES_ARRAY" R8_0603 25929,11667 r270 top locked
RA8 "33R,RES_ARRAY" R8_0603 25685,11313.62 r180 top locked
RA9 "33R,RES_ARRAY" R8_0603 25497.24,11313.62 r180 top locked
RA10 "33R,RES_ARRAY" R8_0603 25309.34,11313.62 r180 top locked
RA11 "33R,RES_ARRAY" R8_0603 25145,11313.62 r180 top locked
Radj1 "Res Tap" RADJ 24620,11915 r180 top locked
S1 "KMR231GLFS" SW4SMD_63X161LS 27048.73,13830 r0 top locked
S2 "KMR231GLFS" SW4SMD_63X161LS 26127,11478.62 r180 top locked
S3 "KMR231GLFS" SW4SMD_63X161LS 26966,13603.62 r90 bottom locked
S4 "KMR231GLFS" SW4SMD_63X161LS 27048.73,14023 r0 top locked
S5 "KMR231GLFS" SW4SMD_63X161LS 27196,12068.38 r0 top locked
S7 "KMR231GLFS" SW4SMD_63X161LS 27313.73,13830 r0 top locked
TP1 "TESTPT1" TP1-8040 25065.12,11485.57 r270 top locked
TP2 "TESTPT1" TP60C_SMD 26157,12897 r90 top locked
TP3 "TESTPT1" TP60C_SMD 26237,12897 r90 top locked
TP4 "TESTPT1" TP1-8040 27171,12787 r270 bottom locked
TP5 "TESTPT1" TP60C33D 26284.12,14269.57 r0 top
TP6 "TESTPT1" TP60C33D 26149.12,14269.57 r90 top
TP7 "TESTPT1" TP60C33D 26019.12,14269.57 r270 top
TP8 "TESTPT1" TP60C33D 25895.12,14269.57 r90 top
TP9 "TESTPT1" TP1-8040 27514,14018.15 r0 top locked
TP10 "TESTPT1" TP1-8040 27615,14018.15 r90 top locked
TP11 "TESTPT1" TP1-8040 25120.12,13000.57 r180 top locked
TP12 "TESTPT1" TP1-8040 26705,13978.95 r90 top locked
TP13 "TESTPT1" TP1-8040 26850,13738.62 r90 top locked
TP14 "TESTPT1" TP1-8040 26725.12,14100.57 r90 top locked
TP15 "TESTPT1" TP1-8040 27950.12,12305.57 r90 top locked
TP16 "TESTPT1" TP1-8040 27378,12061.38 r90 top locked
TP17 "TESTPT1" TP1-8040 27848.34,12305.57 r90 top locked
TP18 "TESTPT1" TP1-8040 26725,11953.62 r90 top locked
TP19 "TESTPT1" TP1-8040 27822,13483 r90 top locked
TP20 "TESTPT1" TP1-8040 27015.5,13103.5 r180 top locked
TP21 "TESTPT1" TP1-8040 27015,13008.62 r180 top locked
TP22 "TESTPT1" TP1-8040 27033,12887 r0 top locked
TP23 "TESTPT1" TP1-8040 27033,12787 r0 top locked
TP24 "TESTPT1" TP1-8040 25697.5,14062 r180 top locked
TP25 "TESTPT1" TP1-8040 25597.5,14062 r270 top locked
TP26 "TESTPT1" TP1-8040 25597.5,14162 r0 top locked
TP27 "TESTPT1" TP1-8040 25497.5,14062 r90 top locked
TP28 "TESTPT1" TP1-8040 25497.5,14162 r180 top locked
TP29 "TESTPT1" TP1-8040 25397.5,14162 r90 top locked
TP30 "TESTPT1" TP1-8040 25297.5,14062 r90 top locked
TP31 "TESTPT1" TP1-8040 25697.5,14162 r90 top locked
TP32 "TESTPT1" TP1-8040 25397.5,14062 r90 top locked
TP33 "TESTPT1" TP1-8040 25297.5,14162 r90 top locked
TP34 "TESTPT1" TP1-8040 27455,13440 r90 top locked
TP35 "TESTPT1" TP1-8040 26875.12,14100.57 r90 top locked
TP36 "TESTPT1" TP1-8040 26635,11953.62 r270 top locked
TP37 "TESTPT1" TP1-8040 26540.12,12924.57 r90 top locked
TP38 "TESTPT1" TP1-8040 26015.12,13745.57 r90 top locked
TP39 "TESTPT1" TP1-8040 27990.56,12918.96 r270 top locked
TP40 "TESTPT1" TP1-8040 27990.56,13133.96 r270 top locked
